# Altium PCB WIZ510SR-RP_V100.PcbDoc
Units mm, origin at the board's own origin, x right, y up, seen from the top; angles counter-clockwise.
Board outline 63 x 45 mm, 4 copper layers (Top Layer, Internal Plane 1, Internal Plane 2, Bottom Layer); 101 components, 119 nets, 372 pads, 369 vias.
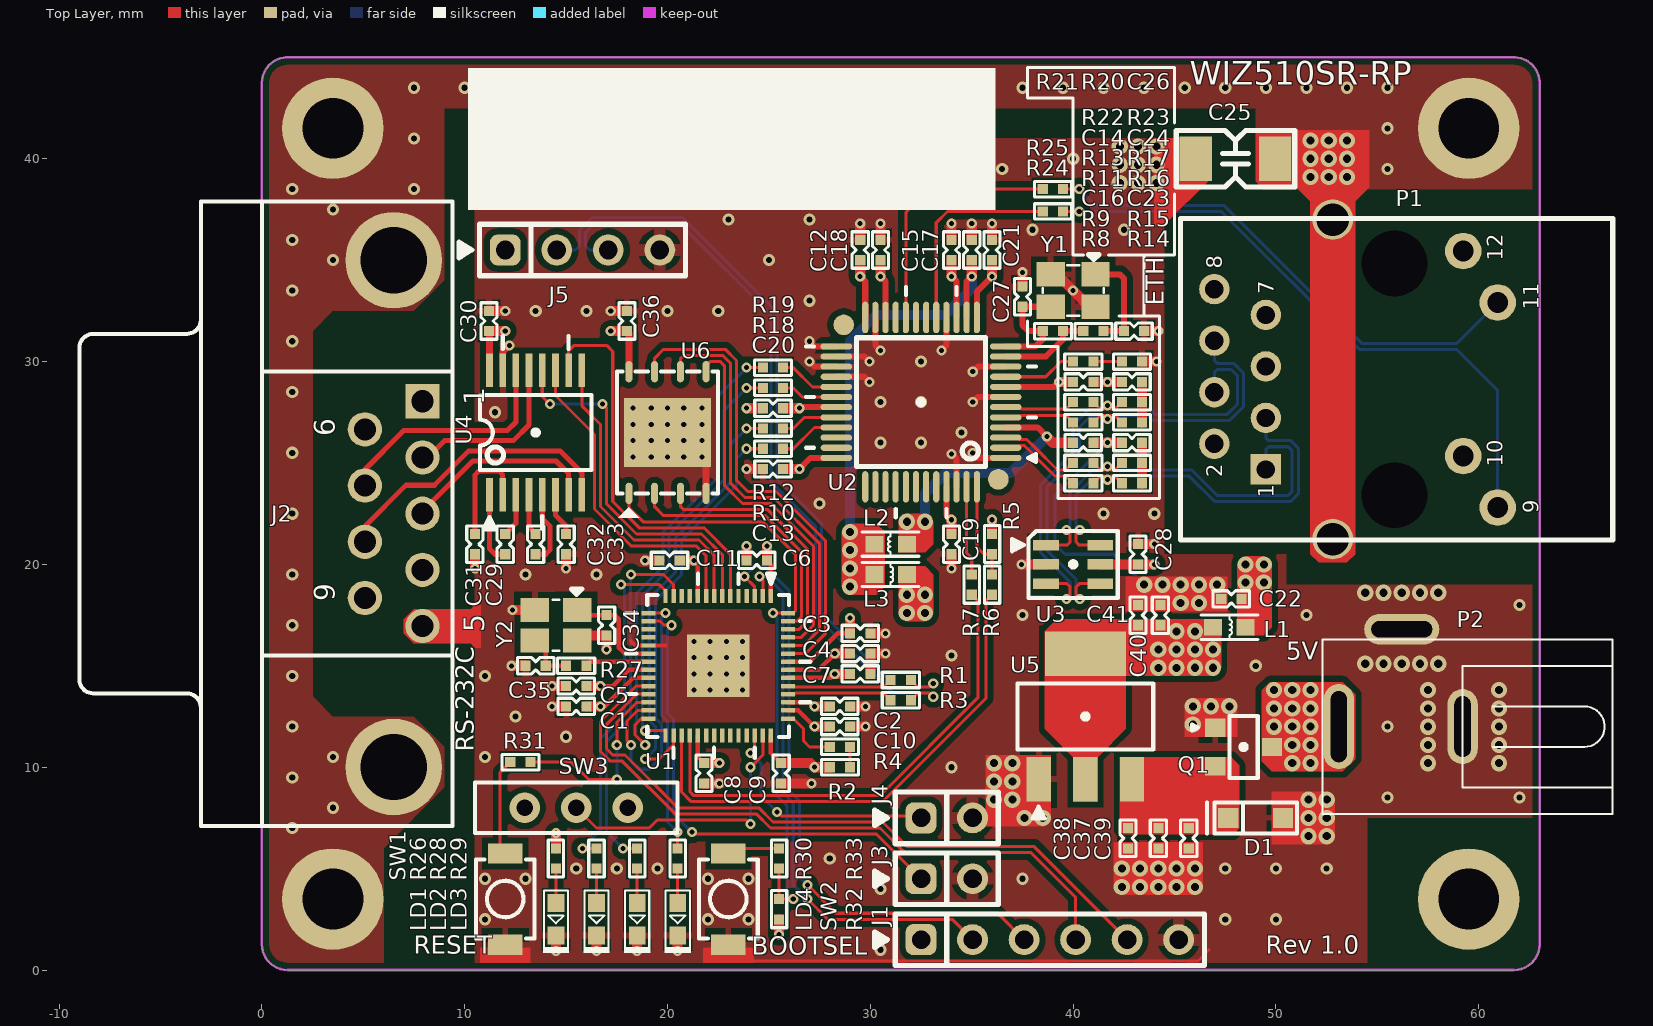
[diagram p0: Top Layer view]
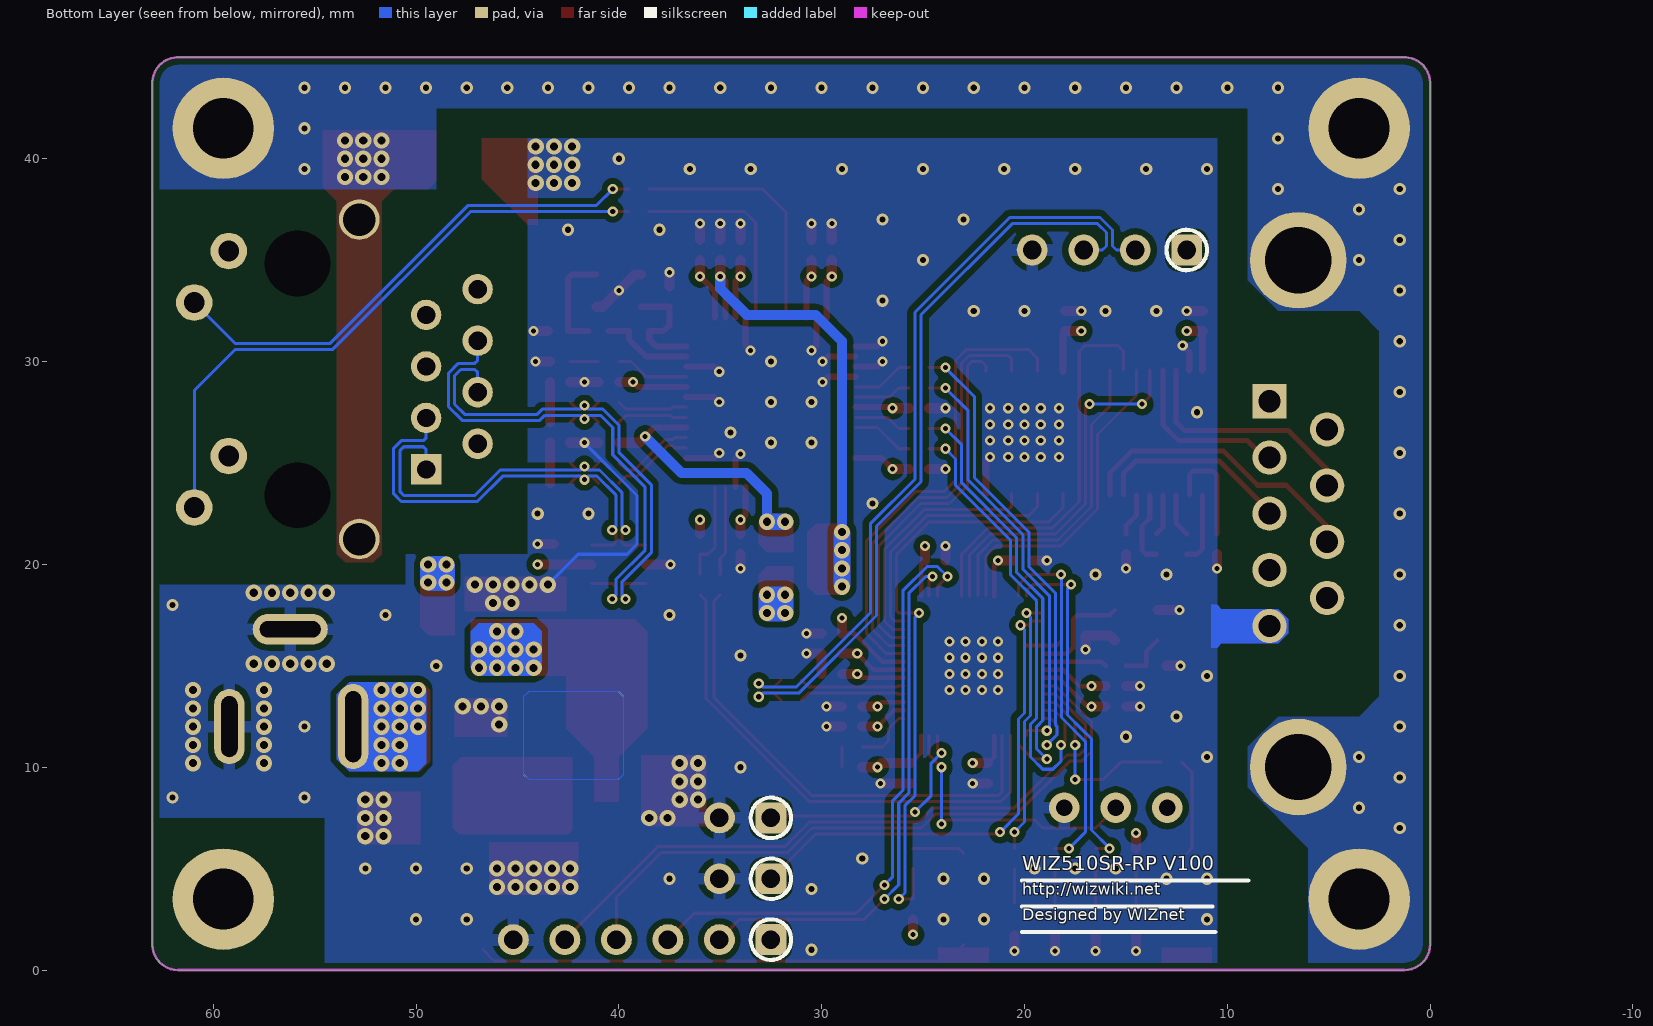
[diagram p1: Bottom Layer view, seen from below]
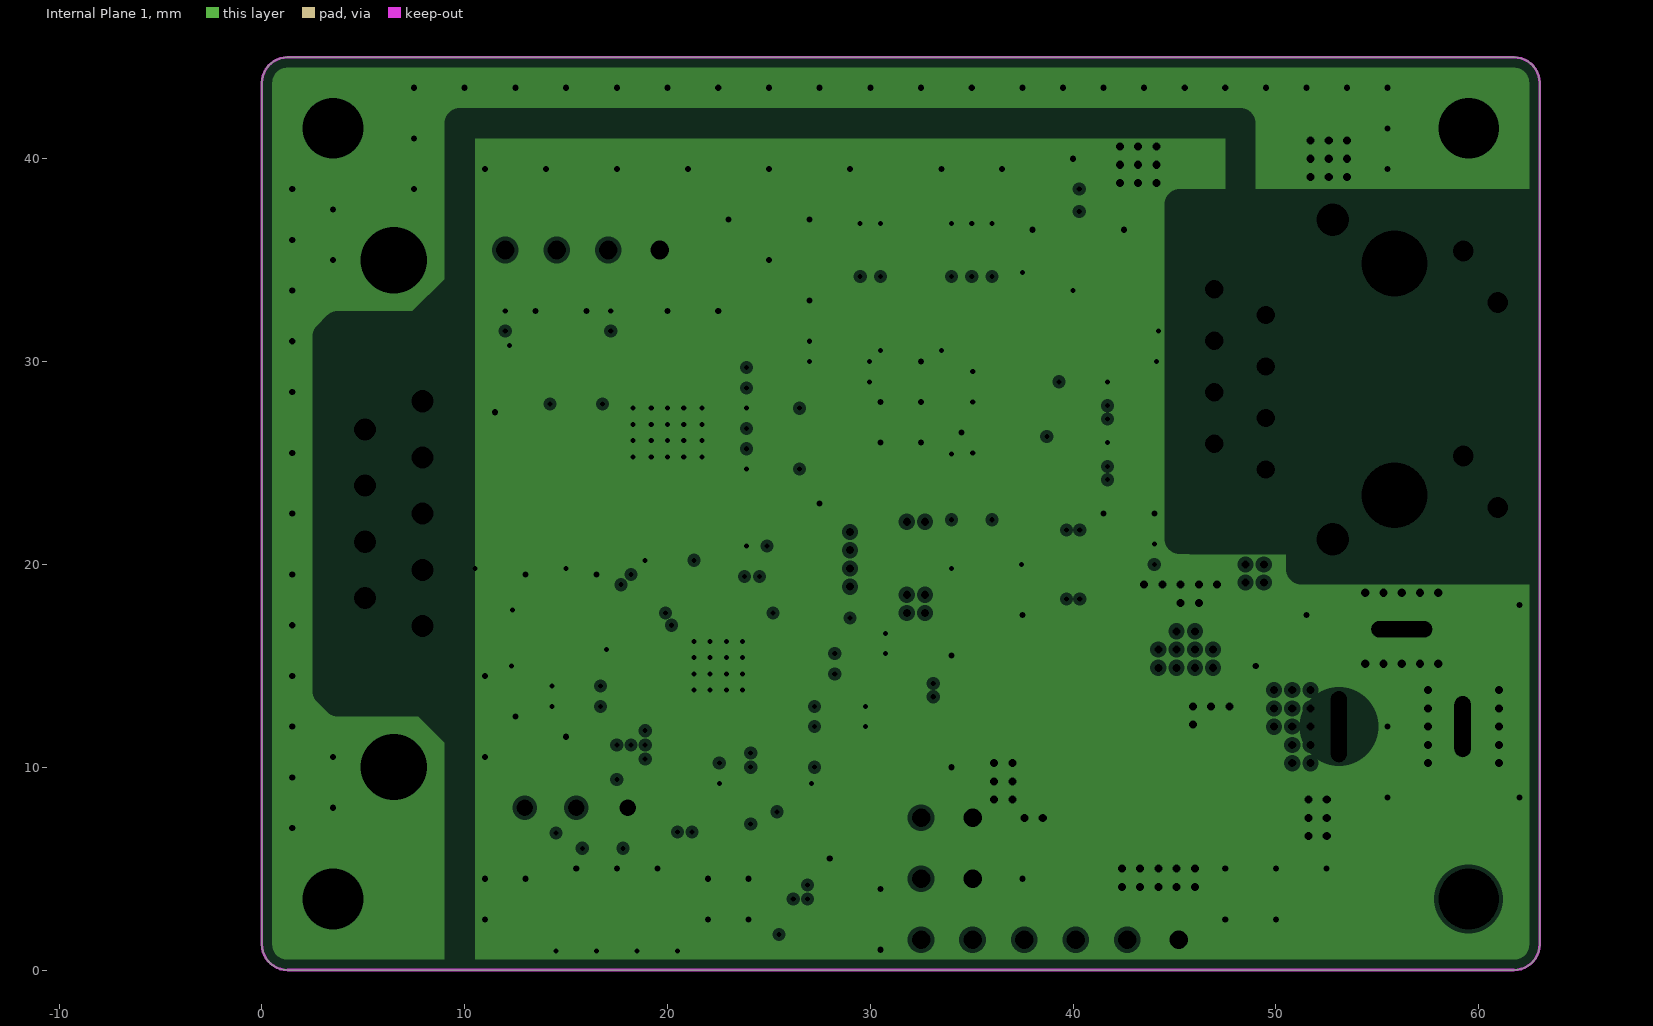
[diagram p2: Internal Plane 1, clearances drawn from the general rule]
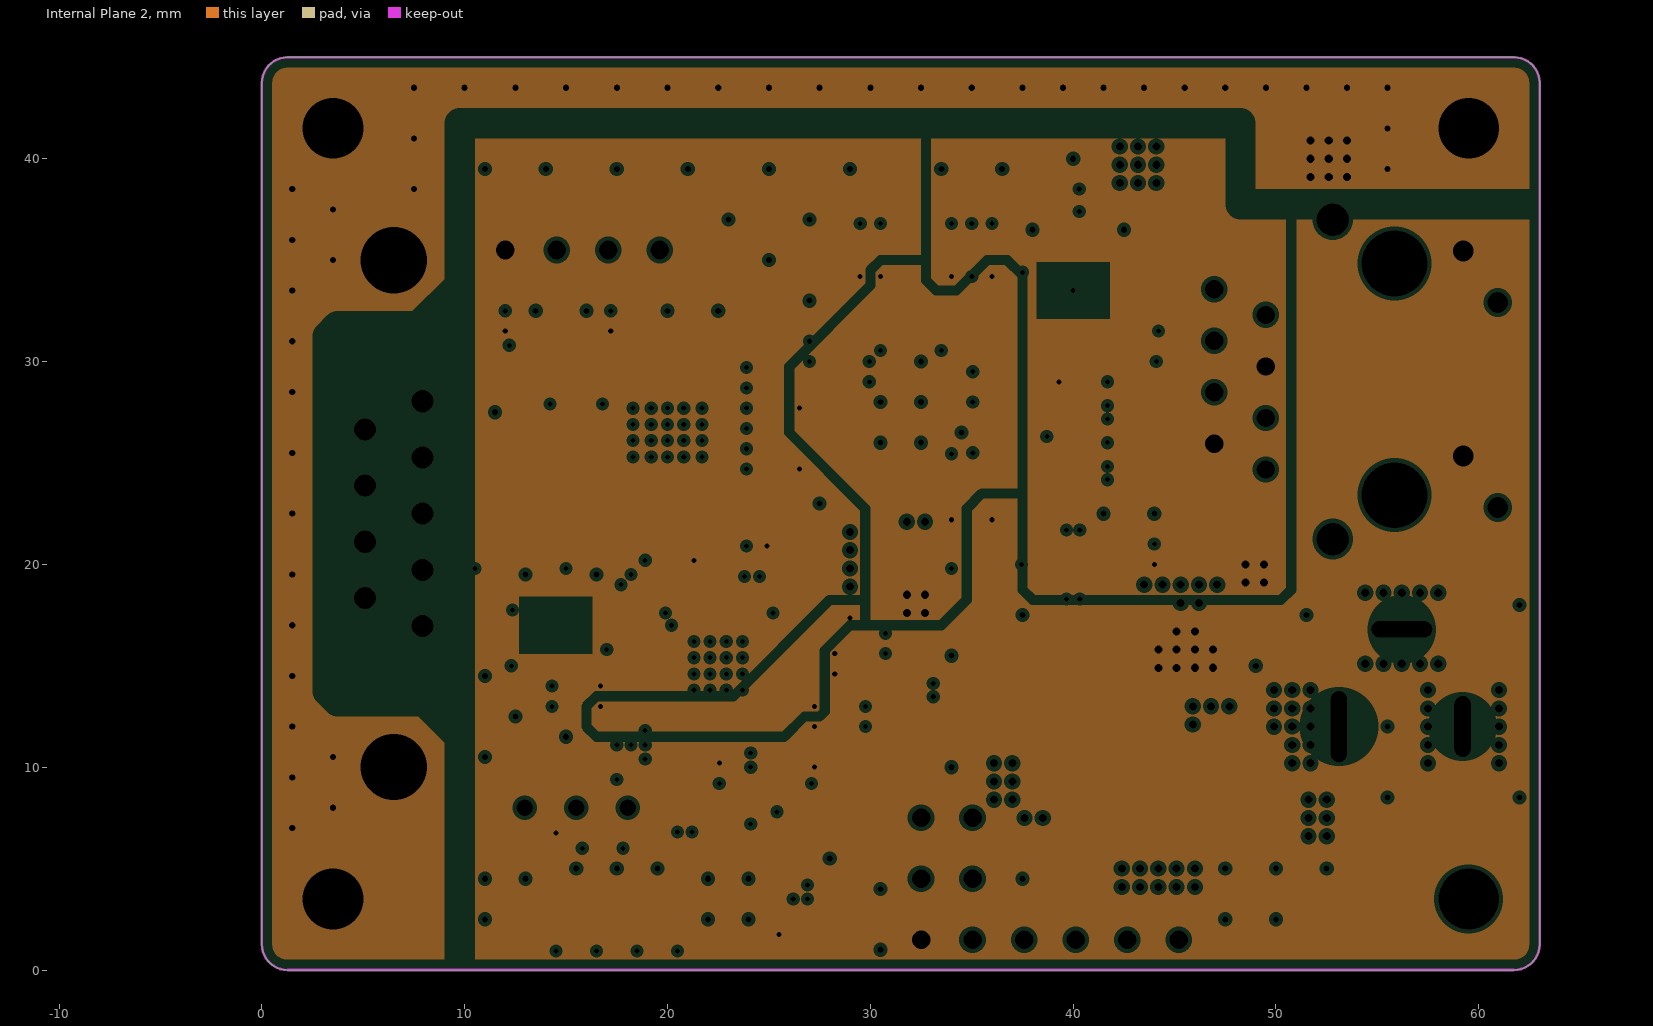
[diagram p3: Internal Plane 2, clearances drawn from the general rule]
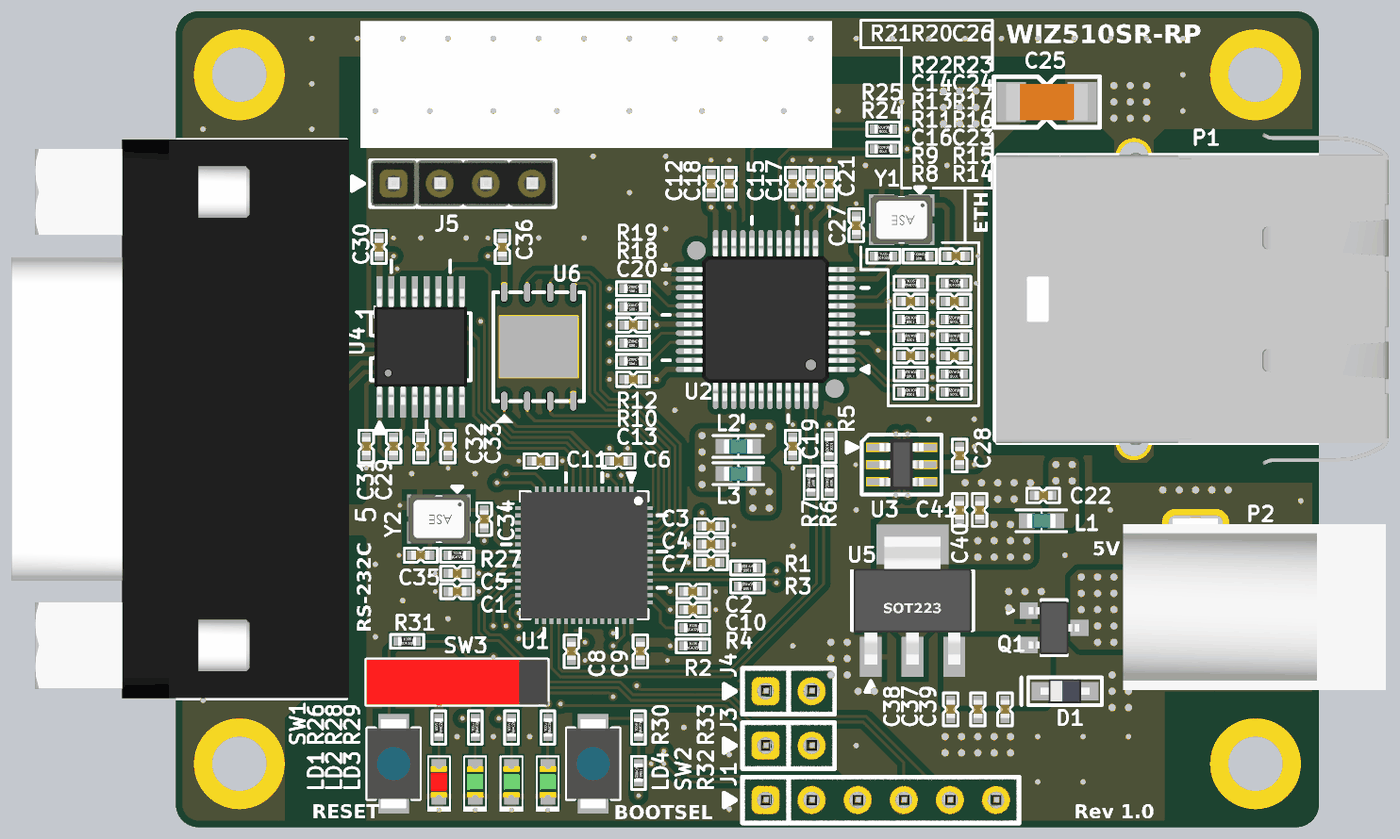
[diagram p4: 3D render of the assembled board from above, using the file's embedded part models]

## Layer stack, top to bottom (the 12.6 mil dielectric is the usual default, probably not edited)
Top Solder: solder mask 0.0102, Solder Resist, Dk 3.5
Top Layer: signal copper 0.0356
Dielectric1: core 0.32, FR-4, Dk 4.8
Internal Plane 1: plane copper 0.0356, net GND
Dielectric5: prepreg 0.32, FR-4, Dk 4.8
Internal Plane 2: plane copper 0.0356, net 3V3
Dielectric6: core 0.32, FR-4, Dk 4.8
Bottom Layer: signal copper 0.0356
Bottom Solder: solder mask 0.0102, Solder Resist, Dk 3.5

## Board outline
0,1.27 0,43.73 cw(c1.27,43.73) 1.27,45 61.73,45 cw(c61.73,43.73) 63,43.73 63,1.27 cw(c61.73,1.27) 61.73,0 1.27,0 cw(c1.27,1.27)

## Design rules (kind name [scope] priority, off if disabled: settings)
Clearance [All] p1: gap=0.15 ignorepadtopadclearanceinfootprint=FALSE except(0: Arc-Hole Track-Hole SMDPad-Hole THPad-Hole Via-Hole Fill-Hole Poly-Hole Region-Hole Text-Hole; 0.3: Arc-Poly Track-Poly SMDPad-Poly THPad-Poly Via-Poly Fill-Poly Poly-Poly Poly-Region Poly-Text)
DiffPairsRouting [All] p1: maxlimit=0.15 minlimit=0.15 mostfreqgap=0.15 toplayer_minwidth=0.15 toplayer_maxwidth=0.15 toplayer_prefwidth=0.15 bottomlayer_minwidth=0.15 bottomlayer_maxwidth=0.15 bottomlayer_prefwidth=0.15 maxuncoupledlength=15.24
HoleSize [All] p1: absolutevalues=TRUE maxlimit=4.064 minlimit=0.025 maxpercent=80.000 minpercent=20.000
PlaneClearance [All] p1: clearance=0.2
PlaneConnect [All] p1: planeconnectstyle=Direct reliefexpansion=0.508 reliefentries=4 reliefconductorwidth=0.254 reliefairgap=0.254
PolygonConnect [All] p1: thpad.connectstyle=Relief thpad.reliefconductorwidth=0.6 thpad.reliefentries=4 thpad.polygonreliefangle="90 Angle" thpad.airgapwidth=0.3 smdpad.connectstyle=Relief smdpad.reliefconductorwidth=0.3 smdpad.reliefentries=4 smdpad.polygonreliefangle="90 Angle" smdpad.airgapwidth=0.3 via.connectstyle=Direct via.reliefconductorwidth=0.254 via.reliefentries=4 via.polygonreliefangle="90 Angle" via.airgapwidth=0.254
RoutingVias [All] p1: holewidth=0.25 width=0.5 viastyle="Through Hole" minholewidth=0.25 minwidth=0.5 maxholewidth=0.4 maxwidth=0.8
SolderMaskExpansion [All] p1: expansion=0 istentingtop=FALSE
Width [All] p1: maxlimit=3 minlimit=0.1 preferedwidth=0.15
26 further rules are at their usual default settings.

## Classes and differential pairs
differential pair USB_U1: +NetR1_2 -NetR3_2
differential pair USB: +USB_DM -USB_DP
differential pair RX_U2: +NetR11_2 -NetR13_2
differential pair TX_U2: +NetR8_2 -NetR9_2
differential pair TX: +TX_P -TX_N
differential pair RX: +RX_P -RX_N

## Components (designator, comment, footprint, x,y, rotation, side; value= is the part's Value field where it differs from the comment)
C1 "1uF" CAP-0402 15.5,13 r0 top
C2 "0.1uF" CAP-0402 28.5,13 r180 top
C3 "0.1uF" CAP-0402 29.5,16.6 r180 top
C4 "1uF" CAP-0402 29.5,15.6 r180 top
C5 "0.1uF" CAP-0402 15.5,14 r0 top
C6 "0.1uF" CAP-0402 24.4,20.2 r0 top
C7 "0.1uF" CAP-0402 29.5,14.6 r180 top
C8 "0.1uF" CAP-0402 21.8,9.7 r90 top
C9 "0.1uF" CAP-0402 25.6,9.7 r90 top
C10 "0.1uF" CAP-0402 28.5,12 r180 top
C11 "0.1uF" CAP-0402 20.1,20.2 r0 top
C12 "0.1uF" CAP-0402 29.5,35.5 r270 top
C13 "0.1uF" CAP-0402 25.2,24.7 r0 top
C14 "0.1uF" CAP-0402 40.5,29 r180 top
C15 "0.1uF" CAP-0402 34,35.5 r270 top
C16 "0.1uF" CAP-0402 40.5,26 r180 top
C17 "1uF" CAP-0402 35,35.5 r270 top
C18 "0.1uF" CAP-0402 30.5,35.5 r270 top
C19 "0.1uF" CAP-0402 34,21 r90 top
C20 "0.1uF" CAP-0402 25.2,27.7 r0 top
C21 "0.1uF" CAP-0402 36,35.5 r270 top
C22 "0.1uF" CAP-0402 47.8,18.3 r0 top
C23 "0.1uF" CAP-0402 42.9,26 r0 top
C24 "0.1uF" CAP-0402 42.9,29 r0 top
C25 "1nF/2kV" CAP-1808 48,40 r0 top
C26 "18pF" CAP-0402 43,31.5 r180 top
C27 "18pF" CAP-0402 37.5,33.2 r270 top
C28 "0.1uF" CAP-0402 43.2,20.5 r270 top
C29 "0.1uF" CAP-0402 12,21 r90 top
C30 "0.1uF" CAP-0402 11.2,32 r270 top
C31 "0.1uF" CAP-0402 10.5,21 r90 top
C32 "0.1uF" CAP-0402 13.5,21 r270 top
C33 "0.1uF" CAP-0402 15,21 r90 top
C34 "15pF" CAP-0402 17,17 r270 top
C35 "15pF" CAP-0402 13.5,15 r180 top
C36 "0.1uF" CAP-0402 18,32 r270 top
C37 "1uF" CAP-0402 44.2,6.5 r90 top
C38 "1uF" CAP-0402 42.7,6.5 r90 top
C39 "0.1uF" CAP-0402 45.7,6.5 r90 top
C40 "1uF" CAP-0402 44.3,17.5 r270 top
C41 "0.1uF" CAP-0402 43.2,17.5 r270 top
D1 "BAT60A" SOD-323(1-C,2-A) 49,7.5 r180 top
J1 "2.54mm 1x6 Pin Header DIP" IDC-1X6 32.5,1.5 r0 top
J2 "D-SUB9-MALE" D-SUB9-MALE -3,22.5 r90 top locked
J3 "2.54mm 1x2 Pin Header DIP" IDC-1X2 32.5,4.5 r0 top
J4 "2.54mm 1x2 Pin Header DIP" IDC-1X2 32.5,7.5 r0 top
J5 "2.54mm 1x4 Pin Header DIP" IDC-1X4 12,35.5 r0 top
L1 "HH-1M1608-121JT" IND-0603 47.7,16.9 r0 top
L2 "HH-1M1608-121JT" IND-0603 31,21 r180 top
L3 "HH-1M1608-121JT" IND-0603 31,19.5 r0 top
LD1 "Red" LED-0603-RED 14.5,2.5 r270 top
LD2 "Green" LED-0603-GREEN 16.5,2.5 r270 top
LD3 "Green" LED-0603-green 18.5,2.5 r270 top
LD4 "Green" LED-0603-GREEN 20.5,2.5 r270 top
P1 "J1B1211CCD" RJ45-J1B1211CCD 63.65,29.125 r90 top locked
P2 "DC-JACK 2pi" "DC-JACK 2pi" 63,12 r90 top locked
Q1 "IRLML6402" SOT-23-3L 48.4,11 r270 top
R1 "0R" RES-0402 31.5,14.3 r180 top
R2 "200R" RES-0402 28.5,10 r0 top
R3 "0R" RES-0402 31.5,13.3 r180 top
R4 "1R" RES-0402 28.5,11 r0 top
R5 "4.7K" RES-0402 36,21 r270 top
R6 "0R" RES-0402 36,19 r270 top
R7 "0R" RES-0402 35,19 r270 top
R8 "3.3R" RES-0402 40.5,24 r180 top
R9 "3.3R" RES-0402 40.5,25 r180 top
R10 "0R" RES-0402 25.2,25.7 r180 top
R11 "3.3R" RES-0402 40.5,27 r180 top
R12 "0R" RES-0402 25.2,26.7 r180 top
R13 "3.3R" RES-0402 40.5,28 r180 top
R14 "49.9R" RES-0402 42.9,24 r180 top
R15 "49.9R" RES-0402 42.9,25 r180 top
R16 "49.9R" RES-0402 42.9,27 r180 top
R17 "49.9R" RES-0402 42.9,28 r180 top
R18 "0R" RES-0402 25.2,28.7 r180 top
R19 "0R" RES-0402 25.2,29.7 r180 top
R20 "0R" RES-0402 41,31.5 r180 top
R21 "1M" RES-0402 39,31.5 r0 top
R22 "12K/1%" RES-0402 40.5,30 r0 top
R23 "300R" RES-0402 42.9,30 r0 top
R24 "470R" RES-0402 39,37.4 r180 top
R25 "470R" RES-0402 39,38.5 r180 top
R26 "470R" RES-0402 14.5,5.5 r90 top
R27 "1K" RES-0402 15.5,15 r0 top
R28 "470R" RES-0402 16.5,5.5 r90 top
R29 "470R" RES-0402 18.5,5.5 r90 top
R30 "470R" RES-0402 20.5,5.5 r90 top
R31 "1K" RES-0402 12.75,10.25 r0 top
R32 "NC" RES-0402 25.5,3 r270 top
R33 "1K" RES-0402 25.5,5.5 r90 top
SW1 "1185SA(2.0)" ST-1185S 12,3.5 r270 top
SW2 "1185SA(2.0)" ST-1185S 23,3.5 r270 top
SW3 "ITS-12H" ITS-12H 15.5,8 r180 top
U1 "RP2040" QFN56(0.4/7X7) 22.5,15 r270 top
U2 "W5100S" LQFP48(0.5/9.0) 32.5,28 r180 top
U3 "TPD4S009DBKR" SOT-23-6L 40,20 r0 top
U4 "SP3232EBEY" TSSOP16(0.65/6.4) 13.5,26.5 r90 top
U5 "AME8815BEGT330Z" SOT-223 40.6,12.5 r0 top
U6 "W25Q16JVZPIM" WSON8(6X5_1.27) 20,26.5 r90 top
Y1 "25MHz" OSC-82J0626 40,33.5 r180 top
Y2 "12MHz" OSC-TZ1067B 14.5,17 r180 top

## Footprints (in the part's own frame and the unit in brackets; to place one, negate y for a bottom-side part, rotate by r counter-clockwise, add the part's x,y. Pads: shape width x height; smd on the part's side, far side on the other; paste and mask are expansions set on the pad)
CAP-0402 [mm]
  rect 0.5x0.5 smd: 1(-0.5,0) 2(0.5,0)
  silkscreen extent -0.9,-0.4 0.9,0.4, body extent -0.48,-0.25 0.52,0.25, height 0.6
CAP-1808 [mm] "Ceramic CAP 1808(4520)"
  rect 1.6x2.2 smd: 1(-1.95,0) 2(1.95,0)
  silkscreen extent -2.92,-1.4 2.92,1.4, body extent -2.25,-1.02 2.25,1.01, height 2
D-SUB9-MALE [mm] "D-SUB9, MALE, Right Angle;"
  rect 1.69x1.69 hole 1.09: 1(5.54,-10.92)
  round 1.69 hole 1.09: 2(2.77,-10.92) 3(0,-10.92) 4(-2.77,-10.92) 5(-5.54,-10.92) 6(4.155,-8.08) 7(1.385,-8.08) 8(-1.385,-8.08) 9(-4.155,-8.08)
  round 4.76 hole 3.26: 10(-12.495,-9.5) 11(12.495,-9.5)
  silkscreen extent -15.4,-12.4 15.4,6, body extent -15.38,-12.55 15.43,6.05, height 12.57
"DC-JACK 2pi" [mm] "DC-JACK 2pi"
  oval 4.2x1.5 hole 0.8 slot 3.5 at 0 deg: 1(0,9.9)
  oval 1.5x3.7 hole 0.8 slot 3 at 90 deg: 2(4.8,6.8)
  oval 3.7x1.5 hole 0.8 slot 3 at 0 deg: 3(0,3.8)
  silkscreen extent -4.3,-3.6 4.3,10.7, body extent -4.42,-3.69 5.05,10.79, height 11.18
IDC-1X2 [mil]
  rrect50% 60x60 hole 36: 1(0,0)
  round 60 hole 36: 2(100,0)
  silkscreen extent -90,-50 150,50, body extent -49,-49 151,51, height 336
IDC-1X4 [mil]
  rrect50% 60x60 hole 36: 1(0,0)
  round 60 hole 36: 2(100,0) 3(200,0) 4(300,0)
  silkscreen extent -90,-50 350,50, body extent -49,-49 351,51, height 336
IDC-1X6 [mil] "6-Way 2.54 mm Male Header"
  rrect50% 60x60 hole 36: 1(0,0)
  round 60 hole 36: 2(100,0) 3(200,0) 4(300,0) 5(400,0) 6(500,0)
  silkscreen extent -90,-50 550,50, body extent -49,-49 551,51, height 336
IND-0603 [mm] "Inductor 0603(1608)"
  rect 0.89x0.82 smd: 1(-0.8,0) 2(0.8,0)
  Top Layer pour cut-out: -0.254,0.508 -0.254,-0.508 0.254,-0.508 0.254,0.508
  silkscreen extent -1.4,-0.6 1.4,0.6, body extent -0.8,-0.4 0.8,0.4, height 0.95
ITS-12H [mm] "Through Hole Slide Switch SPDT On-On 500mA Slide"
  round 1.5 hole 0.8: 1(0,0) 2(2.54,0) 3(-2.54,0)
  silkscreen extent -5,-1.25 5,1.25, body extent -5,-1.25 5,1.25, height 6.4
LED-0603-GREEN [mm] "LED-0603-GREEN"
  rect 0.89x0.82 smd: 1(-0.8,0) 2(0.8,0)
  silkscreen extent -1.41,-0.65 1.65,0.65, body extent -0.85,-0.45 0.85,0.45, height 0.9
LED-0603-green [mm] "LED-0603-GREEN"
  rect 0.89x0.82 smd: 1(-0.8,0) 2(0.8,0)
  silkscreen extent -1.41,-0.65 1.65,0.65, body extent -0.85,-0.45 0.85,0.45, height 0.9
LED-0603-RED [mm] "LED-0603-RED"
  rect 0.89x0.82 smd: 1(-0.8,0) 2(0.8,0)
  silkscreen extent -1.41,-0.65 1.65,0.65, body extent -0.85,-0.45 0.85,0.45, height 0.9
LQFP48(0.5/9.0) [mm]
  round 1.016 smd: 0(-3.81,3.81) 0(3.81,-3.81)
  oval 1.55x0.3 smd: 1(-4.175,2.75) 2(-4.175,2.25) 3(-4.175,1.75) 4(-4.175,1.25) 5(-4.175,0.75) 6(-4.175,0.25) 7(-4.175,-0.25) 8(-4.175,-0.75) 9(-4.175,-1.25) 10(-4.175,-1.75) 11(-4.175,-2.25) 12(-4.175,-2.75) 25(4.175,-2.75) 26(4.175,-2.25) 27(4.175,-1.75) 28(4.175,-1.25) 29(4.175,-0.75) 30(4.175,-0.25) 31(4.175,0.25) 32(4.175,0.75) 33(4.175,1.25) 34(4.175,1.75) 35(4.175,2.25) 36(4.175,2.75)
  oval 0.3x1.55 smd: 13(-2.75,-4.175) 14(-2.25,-4.175) 15(-1.75,-4.175) 16(-1.25,-4.175) 17(-0.75,-4.175) 18(-0.25,-4.175) 19(0.25,-4.175) 20(0.75,-4.175) 21(1.25,-4.175) 22(1.75,-4.175) 23(2.25,-4.175) 24(2.75,-4.175) 37(2.75,4.175) 38(2.25,4.175) 39(1.75,4.175) 40(1.25,4.175) 41(0.75,4.175) 42(0.25,4.175) 43(-0.25,4.175) 44(-0.75,4.175) 45(-1.25,4.175) 46(-1.75,4.175) 47(-2.25,4.175) 48(-2.75,4.175)
  silkscreen extent -5.67,-5.67 5.68,5.68, body extent -4.5,-4.5 4.5,4.5, height 1.5
OSC-82J0626 [mm]
  rect 1.4x1.2 smd: 1(-1.1,-0.8) 2(1.1,-0.8) 3(1.1,0.8) 4(-1.1,0.8)
  silkscreen extent -1.5,-1.78 1.5,1.25, body extent -1.7,-1.35 1.7,1.35, height 1.06
OSC-TZ1067B [mm]
  rect 1.4x1.2 smd: 1(-1.05,-0.75) 2(1.05,-0.75) 3(1.05,0.75) 4(-1.05,0.75)
  silkscreen extent -1.27,-1.78 0.15,1.25, body extent -1.7,-1.35 1.7,1.35, height 1.06
QFN56(0.4/7X7) [mm]
  rect 0.7x0.22 smd: 1(-3.44,2.6) 2(-3.44,2.2) 3(-3.44,1.8) 4(-3.44,1.4) 5(-3.44,1) 6(-3.44,0.6) 7(-3.44,0.2) 8(-3.44,-0.2) 9(-3.44,-0.6) 10(-3.44,-1) 11(-3.44,-1.4) 12(-3.44,-1.8) 13(-3.44,-2.2) 14(-3.44,-2.6) 29(3.44,-2.6) 30(3.44,-2.2) 31(3.44,-1.8) 32(3.44,-1.4) 33(3.44,-1) 34(3.44,-0.6) 35(3.44,-0.2) 36(3.44,0.2) 37(3.44,0.6) 38(3.44,1) 39(3.44,1.4) 40(3.44,1.8) 41(3.44,2.2) 42(3.44,2.6)
  rect 0.22x0.7 smd: 15(-2.6,-3.44) 16(-2.2,-3.44) 17(-1.8,-3.44) 18(-1.4,-3.44) 19(-1,-3.44) 20(-0.6,-3.44) 21(-0.2,-3.44) 22(0.2,-3.44) 23(0.6,-3.44) 24(1,-3.44) 25(1.4,-3.44) 26(1.8,-3.44) 27(2.2,-3.44) 28(2.6,-3.44) 43(2.6,3.44) 44(2.2,3.44) 45(1.8,3.44) 46(1.4,3.44) 47(1,3.44) 48(0.6,3.44) 49(0.2,3.44) 50(-0.2,3.44) 51(-0.6,3.44) 52(-1,3.44) 53(-1.4,3.44) 54(-1.8,3.44) 55(-2.2,3.44) 56(-2.6,3.44)
  rect 3.1x3.1 smd: 57(0,0)
  silkscreen extent -4.54,-4.54 4.54,4.54, body extent -3.5,-3.5 3.5,3.5, height 0.8
RES-0402 [mm]
  rect 0.5x0.5 smd: 1(-0.5,0) 2(0.5,0)
  silkscreen extent -0.91,-0.38 0.91,0.38, body extent -0.5,-0.25 0.5,0.25, height 0.35
RJ45-J1B1211CCD [mm]
  rect 1.5x1.5 hole 0.9: 1(-4.445,14.15)
  round 1.5 hole 0.9: 2(-3.175,16.69) 3(-1.905,14.15) 4(-0.635,16.69) 5(0.635,14.15) 6(1.905,16.69) 7(3.175,14.15) 8(4.445,16.69)
  round 1.8 hole 1.02: 9(-6.325,2.72) 10(-3.785,4.42) 11(3.785,2.72) 12(6.325,4.42)
  round 2 hole 1.6: 13(-7.875,10.85) 14(7.875,10.85)
  round 1.8 hole 3.25: ""(-5.715,7.8) ""(5.715,7.8)
  silkscreen extent -7.93,-2.95 7.93,18.35, body extent -9.16,-3.2 9.16,18.64, height 15.09
SOD-323(1-C,2-A) [mm]
  rect 1x1 smd: 1(1.35,0) 2(-1.35,0)
  silkscreen extent -2.03,-0.76 2.4,0.76, body extent -1.35,-0.68 1.35,0.67, height 0.79
SOT-23-3L [mm]
  rect 0.9x1 smd: 1(-0.95,-1.4) 2(0.95,-1.4) 3(0,1.4)
  silkscreen extent -1.53,-2.55 1.53,0.7, body extent -1.45,-1.4 1.45,1.4, height 1.28
SOT-23-6L [mm]
  rect 1.27x0.508 smd paste-0.07: 1(-1.34,0.95) 2(-1.34,0) 3(-1.34,-0.95) 4(1.34,-0.95) 5(1.34,0) 6(1.34,0.95)
  silkscreen extent -3.02,-1.65 2.2,1.65, body extent -1.21,-1.4 1.21,1.4, height 1.09
SOT-223 [mm]
  rect 1.2x2.2 smd: 1(-2.3,-3.1) 2(0,-3.1) 3(2.3,-3.1)
  rect 4x2.2 smd: 4(0,3.1)
  silkscreen extent -3.35,-5.03 3.35,1.63, body extent -3.25,-3.53 3.25,3.52, height 1.82
ST-1185S [mm]
  rect 1x1.7 smd: 1(-2.25,0) 2(2.25,0)
  silkscreen extent -1.95,-1.45 1.95,1.45, body extent -2.45,-1.45 2.45,1.45, height 2
TSSOP16(0.65/6.4) [mil]
  rect 65x13 smd: 1(-121.04,89.57) 2(-121.04,63.98) 3(-121.04,38.39) 4(-121.04,12.8) 5(-121.04,-12.8) 6(-121.04,-38.39) 7(-121.04,-63.98) 8(-121.04,-89.57) 9(121.04,-89.57) 10(121.04,-63.98) 11(121.04,-38.39) 12(121.04,-12.8) 13(121.04,12.8) 14(121.04,38.39) 15(121.04,63.98) 16(121.04,89.57)
  silkscreen extent -188,-108 187,108, body extent -126,-100 126,100, height 47
WSON8(6X5_1.27) [mm]
  oval 1.05x0.35 smd mask+0.05: 1(-3,1.905) 2(-3,0.635) 3(-3,-0.635) 4(-3,-1.905) 5(3,-1.905) 6(3,-0.635) 7(3,0.635) 8(3,1.905)
  rect 3.4x4.3 smd mask+0.05: 9(0,0)
  silkscreen extent -4.2,-2.5 3,2.5, body extent -3,-2.5 3,2.5, height 0.8

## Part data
C1 C2 C3 C4 C5 C6 C7 C8 C9 C10 C11 C12 C13 C14 C15 C16 C17 C18 C19 C20 C21 C22 C23 C24 C26 C27 C28 C29 C30 C31 C32 C33 C34 C35 C36 C37 C38 C39 C40 C41: library part CAP-0402, "Ceramic CAP 0402(1005)"
C25: library part CAP-1808, "Ceramic CAP 1808(4520)"
D1: library part DIODE-BAT60A, "Silicon Schottky Diode"
J2: "D-SUB-9, MALE,  Right Angle", PackageDocument=O
L1 L2 L3: library part IND-0603, "Inductor 0603(1608)"
LD1 LD2 LD3 LD4: library part LED-0603, "LED-0603"
Q1: library part Q-IRLML6402, "HEXFET Power MOSFET"
R1 R2 R3 R4 R5 R6 R7 R8 R9 R10 R11 R12 R13 R14 R15 R16 R17 R18 R19 R20 R21 R22 R23 R24 R25 R26 R27 R28 R29 R30 R31 R32 R33: library part RES-0402, "RES-0402"
SW1 SW2: library part ITS-1107(SMD), "TACT Switch (SMD)"
SW3: "Slide Switch"
U1: "Raspverry Pi, Dual ARM Cortex-M0+ @ 133MHz"
U2: "WIZnet Hardwired TCP/IP Chip"
U3: "4-Channel ESD Solution for High-Speed Differential Interface"
U4: "True +3.0V to +5.5V RS-232 Transceivers"
U5: "1.5A CMOS LDO"
U6: "3V 16M-BIT / SERIAL FLASH MEMORY WITH / DUAL/QUAD SPI, QPI & DTR"
Y1: library part OSC-82J0626-25MHz, "X-tal 25MHz,3.2x2.5 SMD, CL=18pF"
Y2: library part OSC-TZ1067B-12MHz, "X-tal 12MHz,3.2x2.5 SMD, CL=20pF"

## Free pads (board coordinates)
  round 5 hole 3: 0(3.5,3.5) 0(3.5,41.5) 0(59.5,3.5) 0(59.5,41.5)

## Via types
v1: diameter 0.5, hole 0.25, Top Layer to Bottom Layer, tented both sides, 153 vias
v2: diameter 0.8, hole 0.4, Top Layer to Bottom Layer, tented both sides, 110 vias
v3: diameter 0.6, hole 0.3, Top Layer to Bottom Layer, tented both sides, 106 vias

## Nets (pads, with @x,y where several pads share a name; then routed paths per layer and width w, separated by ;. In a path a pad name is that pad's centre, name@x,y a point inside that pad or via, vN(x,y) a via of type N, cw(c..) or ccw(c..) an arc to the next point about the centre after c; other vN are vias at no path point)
1V1: C1.2 C2.2 C3.2 U1.23 U1.45 U1.50 | length 10.2
  Top Layer w0.22: v1(16.7,13) 16.9,13 18.3,14.4 U1.23 ; U1.45 27.046,13.2 v1(27.246,13) ; U1.50 27,15.2 28.4,16.6 C3.2
  Top Layer w0.5: C1.2 v1(16.7,13) ; v1(27.246,13) C2.2 ; C3.2 v1(29,17.354)
1V2A: C16.2 L2.1 U2.4 | length 13.1
  Top Layer w0.3: U2.4 38.25,26.75 v1(38.7,26.3)
  Top Layer w0.5: v1(38.7,26.3) 39,26 C16.2
  Bottom Layer w0.5: v2(32.7,22.1) 32.7,23.5 33.7,24.5 36.9,24.5 v1(38.7,26.3)
  Bottom Layer w0.8: v2(31.8,22.1) v2(32.7,22.1)
1V2D: C18.2 C19.2 C20.2 C21.2 L3.2 U2.13 U2.22 U2.31 U2.45 | length 11.1
  Top Layer w0.3: v1(26.5,27.7) 26.55,27.75 U2.31 ; v1(30.5,34.2) 30.75,33.95 U2.22 ; U2.45 33.75,22.45 v1(34,22.2) ; U2.13 35.25,33.45 v1(36,34.2)
  Top Layer w0.5: C20.2 v1(26.5,27.7) ; v1(30.5,34.2) C18.2 ; C19.2 v1(34,22.2) ; v1(36,34.2) C21.2
  other v2: 31.8,17.6 32.7,17.6 31.8,18.5 32.7,18.5
1V2O: C17.2 L2.2 L3.1 U2.14 | length 20
  Top Layer w0.3: U2.14 34.75,33.95 v1(35,34.2)
  Top Layer w0.5: v1(35,34.2) C17.2
  Bottom Layer w0.5: v2(29,21.6) 29,31 30.3,32.3 33.7,32.3 35,33.6 v1(35,34.2)
  other v2: 29,18.9 29,19.8 29,20.7
3V3: C4.2 C5.2 C6.2 C7.2 C8.2 C9.2 C10.2 C11.2 C12.2 C13.2 C30.2 C36.2 C40.2 C41.2 J1.1 J5.1 L1.1 P1.10 P1.12 R2.1 R5.1 R26.2 R32.2 U1.1 U1.10 U1.22 U1.33 U1.42 U1.44 U1.48 U1.49 U2.24 U2.36 U4.16 U5.2 U5.4 U6.8 | length 37
  Top Layer w0.22: v1(16.7,14) 17.3,14 18.1,14.8 U1.22 ; v1(21.3,20.2) 21.5,20 U1.10 ; U1.33 21.5,10.5 C8.2 ; C6.2 25.1,20 U1.1 ; U1.42 25.1,10.7 C9.2 ; U1.44 26.446,12.8 v1(27.246,12) ; U1.48 28.046,14.4 v1(28.246,14.6) ; U1.49 27.446,14.8 v1(28.246,15.6)
  Top Layer w0.3: v1(26.5,24.7) 27.05,25.25 U2.36 ; v1(29.5,34.2) 29.75,33.95 U2.24
  Top Layer w0.33: U4.16 C30.2@11.225,31.275
  Top Layer w0.35: C36.2 18.095,31.405 U6.8
  Top Layer w0.5: C30.2 v1(12,31.5) ; R26.2 v1(14.5,6.754) ; C5.2 v1(16.7,14) ; v1(17.2,31.5) C36.2 ; C11.2 v1(21.3,20.2) ; C8.2 v1(22.554,10.2) ; C6.2 v1(24.9,20.9) ; v1(25.5,1.746) R32.2 ; C9.2 27.046,10.2 v1(27.246,10) R2.1 ; C13.2 v1(26.5,24.7) ; v1(27.246,12) C10.2 ; v1(28.246,14.6) C7.2 ; v1(28.246,15.6) C4.2 ; v1(29.5,34.2) C12.2 ; R5.1 v1(36,22.2)
  other v2: 44.2,14.9 45.1,14.9 46,14.901 46.9,14.901 44.2,15.8 45.1,15.8 46,15.8 46.9,15.8 45.1,16.7 46,16.7
3V3A: C14.2 C15.2 C22.2 C28.2 L1.2 P1.2 P1.5 U2.8 U2.15 U3.5 | length 9
  Top Layer w0.3: v1(34,34.2) 34.25,33.95 U2.15 ; U2.8 39.05,28.75 v1(39.3,29)
  Top Layer w0.5: v1(34,34.2) C15.2 ; v1(39.3,29) C14.2 ; U3.5 C28.2 v1(44,20)
  other v2: 48.5,19.1 49.4,19.1 48.5,20 49.4,20
5V: C37.2 C38.2 C39.2 D1.1 Q1.2 U5.3
ACTn: R25.2 U2.20 | length 12.4
  Top Layer w0.15: U2.20 31.75,37.35 32.9,38.5 R25.2
ADC_VREF: R2.2 R4.2 | length 1
  Top Layer w0.15: R2.2 R4.2
BLINK: R30.2 U1.15 | length 12.9
  Top Layer w0.15: U1.15 v1(19.9,17.6) ; R30.2 v1(20.5,6.8)
  Bottom Layer w0.15: v1(19.9,17.6) 19.7,17.4 19.7,12.549 20,12.249 20,7.3 v1(20.5,6.8)
BOOTSEL: R32.1 R33.1 U1.56 U6.1 | length 30.5
  Top Layer w0.15: U6.1 18.095,22.805 18.8,22.1 24.7,22.1 26.3,20.5 26.3,17.7 26.2,17.6 U1.56 v1(25.2,17.6) ; R33.1 R32.1 v1(26.2,3.5)
  Bottom Layer w0.15: v1(25.2,17.6) 25.4,17.4 25.4,8.6 25.9,8.1 25.9,3.8 v1(26.2,3.5)
CHGND: C25.2 J2.10 J2.11 P1.13 P1.14 pad.0@3.5,3.5 pad.0@3.5,41.5 pad.0@59.5,41.5
  other v2: 51.7,39.1 52.6,39.1 53.5,39.1 51.7,40 52.6,40 53.5,40 51.7,40.9 52.6,40.9 53.5,40.9
  other v3: 1.5,7 3.5,8 1.5,9.5 3.5,10.5 1.5,12 1.5,14.5 1.5,17 1.5,19.5 1.5,22.5 1.5,25.5 1.5,28.5 1.5,31 1.5,33.5 3.5,35 1.5,36 3.5,37.5 1.5,38.5 7.5,38.5 55.5,39.5 7.5,41 55.5,41.5 7.5,43.5 10,43.5 12.5,43.5 15,43.5 17.5,43.5 20,43.5 22.5,43.5 25,43.5 27.5,43.5 30,43.5 32.5,43.5 35,43.5 37.5,43.5 39.5,43.5 41.5,43.5 43.5,43.5 45.5,43.5 47.5,43.5 49.5,43.5 51.5,43.5 53.5,43.5 55.5,43.5
FACT_RST: J4.1 U1.40 | length 11.6
  Top Layer w0.15: v1(24.1,10.7) 24.3,10.9 U1.40 ; v1(25.4,7.8) 25.6,7.6 32.4,7.6 J4.1
  Bottom Layer w0.15: v1(24.1,10.7) 24.6,10.2 24.6,8.6 v1(25.4,7.8)
GND: C1.1 C2.1 C3.1 C4.1 C5.1 C6.1 C7.1 C8.1 C9.1 C10.1 C11.1 C12.1 C13.1 C14.1 C15.1 C16.1 C17.1 C18.1 C19.1 C20.1 C21.1 C22.1 C23.1 C24.1 C25.1 C26.1 C27.1 C28.1 C30.1 C31.1 C33.1 C34.2 C35.2 C36.1 C37.1 C38.1 C39.1 C40.1 C41.1 D1.2 J1.6 J2.5 J3.2 J4.2 J5.4 LD1.2 LD2.2 LD3.2 LD4.2 P2.2 P2.3 Q1.1 R23.2 SW1.2 SW2.2 SW3.3 U1.19 U1.57 U2.1 U2.7 U2.10 U2.16 U2.23 U2.25 U2.26 U2.27 U2.28 U2.46 U3.2 U4.15 U5.1 U6.4 U6.9 Y1.2 Y1.4 Y2.2 Y2.4 | length 92.2
  Top Layer w0.15: SW2.2 23.8,0.45 46.15,0.45 46.7,1
  Top Layer w0.22: 18.2,16.2 18.4,16 U1.19 19.9,16
  Top Layer w0.3: v1(27,30) 27.25,29.75 U2.27 ; v1(27,31) 27.25,30.75 U2.25 ; U2.28 29.7,29.25 v1(29.95,29) ; U2.26 29.7,30.25 v1(29.95,30) ; U2.23 30.25,30.8 v1(30.5,30.55) ; v1(33.5,30.55) 33.75,30.8 U2.16 ; v1(34,25.45) 34.25,25.2 U2.46 ; v1(35.05,25.5) 35.3,25.25 U2.1 ; v1(35.05,28) 35.3,28.25 U2.7 ; v1(35.05,29.5) 35.3,29.75 U2.10
  Top Layer w0.33: U4.15 11.875,30.475 v1(12.2,30.8)
  Top Layer w0.35: v1(21.7,25.3) 21.905,25.095 U6.4
  Top Layer w0.5: v1(10.5,19.8) C31.1 ; C30.1 v1(12,32.5) ; v1(12.3,15) C35.2 ; v1(12.35,17.75) Y2.2 ; v1(14.3,13) C1.1 ; v1(14.3,14) C5.1 ; v1(14.5,0.946) LD1.2 ; v1(15,19.8) C33.1 ; Y2.4 15.8,16.5 C34.2 v1(17,15.8) ; v1(16.5,0.946) LD2.2 ; v1(17.2,32.5) C36.1 ; v1(18.5,0.946) LD3.2 ; v1(18.9,20.2) C11.1 ; v1(20.5,0.946) LD4.2 ; C8.1 v1(22.554,9.2) ; C6.1 v1(23.9,20.9) ; v1(23.9,24.7) C13.1 ; v1(23.9,27.7) C20.1 ; C9.1 v1(27.1,9.2) ; C10.1 v1(29.754,12) ; C2.1 v1(29.754,13) ; C12.1 v1(29.5,36.8) ; C7.1 C4.1@30,15.354 ; C4.1 v1(30.754,15.6) ; C3.1 v1(30.754,16.6) ; C18.1 v1(30.5,36.8) ; v1(34,19.8) C19.1 ; C15.1 v1(34,36.8) ; C17.1 v1(35,36.8) ; C21.1 v1(36,36.8) ; v1(37.46,20) U3.2 ; C27.1 v1(37.5,34.4) ; Y1.2 39.2,34.3 v1(40,33.5) 40.8,32.7 Y1.4 ; C16.1 v1(41.7,26) C23.1 ; C14.1 v1(41.7,29) C24.1 ; C28.1 v1(44,21) ; R23.2 v1(44.1,30) ; C26.1 v1(44.2,31.5)
  Bottom Layer w0.15: v1(41.7,26) 39.1,23.4 39.1,21 39.6,20.5 42,20.5 v2(43.5,19)
  other v1: 21.3,13.8 22.1,13.8 22.9,13.8 23.7,13.8 21.3,14.6 22.1,14.6 22.9,14.6 23.7,14.6 21.3,15.4 22.1,15.4 22.9,15.4 23.7,15.4 21.3,16.2 22.1,16.2 22.9,16.2 23.7,16.2 18.3,25.3 19.2,25.3 20,25.3 20.8,25.3 18.3,26.1 19.2,26.1 20,26.1 20.8,26.1 21.7,26.1 18.3,26.9 19.2,26.9 20,26.9 20.8,26.9 21.7,26.9 18.3,27.7 19.2,27.7 20,27.7 20.8,27.7 21.7,27.7
  other v2: 42.4,4.1 43.3,4.1 44.2,4.1 45.1,4.1 46,4.1 42.4,5 43.3,5 44.2,5 45.1,5 46,5 51.6,6.6 52.5,6.6 37.6,7.5 38.5,7.5 51.6,7.5 52.5,7.5 36.1,8.4 37,8.4 51.6,8.4 52.5,8.4 36.1,9.3 37,9.3 36.1,10.2 37,10.2 57.5,10.2 61,10.2 57.5,11.1 61,11.1 57.5,12 61,12 45.9,12.1 57.5,12.9 61,12.9 45.9,13 46.8,13 47.7,13 57.5,13.8 61,13.8 54.4,15.1 55.3,15.1 56.2,15.1 57.1,15.1 58,15.1 45.3,18.1 46.2,18.1 54.4,18.6 55.3,18.6 56.2,18.6 57.1,18.6 58,18.6 44.4,19 45.3,19 46.2,19 47.1,19 42.3,38.8 43.2,38.8 44.1,38.8 42.3,39.7 43.2,39.7 44.1,39.7 42.3,40.6 43.2,40.6 44.1,40.6
  other v3: 30.5,1 11,2.5 22,2.5 24,2.5 47.5,2.5 50,2.5 30.5,4 11,4.5 13,4.5 22,4.5 24,4.5 37.5,4.5 15.5,5 17.5,5 19.5,5 47.5,5 50,5 52.5,5 28,5.5 55.5,8.5 62,8.5 34,10 11,10.5 15,11.5 55.5,12 12.5,12.5 11,14.5 49,15 34,15.5 37.5,17.5 51.5,17.5 62,18 13,19.5 16.5,19.5 41.5,22.5 44,22.5 27.5,23 30.5,26 32.5,26 34.5,26.5 11.5,27.5 30.5,28 32.5,28 32.5,30 13.5,32.5 16,32.5 20,32.5 22.5,32.5 27,33 25,35 38,36.5 42.5,36.5 23,37 27,37 11,39.5 14,39.5 17.5,39.5 21,39.5 25,39.5 29,39.5 33.5,39.5 36.5,39.5 40,40
HW_TRIG: SW3.1 U1.41 | length 13.9
  Top Layer w0.15: SW3.1 16.5,7 19.1,7 19.5,7.4 23.9,7.4 v1(24.1,7.2) ; v1(24.1,10) 24.7,10.6 U1.41
  Bottom Layer w0.15: v1(24.1,7.2) v1(24.1,10)
INTn: R7.2 U1.32 | length 24.2
  Top Layer w0.15: U1.32 21.1,8.8 21.3,8.6 30.476,8.6 35.3,13.424 35.3,18.2 R7.2
LINK_STATUS: R29.2 U1.13 | length 17.9
  Top Layer w0.15: v1(17.8,6) R29.2 ; v1(18.2,19.5) 19.8,19.5 20.3,19 U1.13
  Bottom Layer w0.15: v1(17.8,6) 17,6.8 17,11.272 18.175,12.447 18.175,19.475 v1(18.2,19.5)
LINKn: R24.2 U2.17 | length 10.2
  Top Layer w0.15: U2.17 33.25,36.85 33.8,37.4 R24.2
NetC23_2: C23.2 R14.1 R15.1 | length 2
  Top Layer w0.5: R14.1 R15.1 C23.2
NetC24_2: C24.2 R16.1 R17.1 | length 2
  Top Layer w0.5: R16.1 R17.1 C24.2
NetC26_2: C26.2 R20.1 Y1.1 | length 5.1
  Top Layer w0.3: Y1.1 42.3,34.3 42.5,34.1 C26.2 R20.1
NetC27_2: C27.2 R21.1 U2.12 Y1.3 | length 5.8
  Top Layer w0.3: U2.12 38.15,30.75 38.5,31.1 R21.1 37.8,31.5 37.5,31.8 C27.2 Y1.3
NetC29_1: C29.1 U4.1 | length 3.5
  Top Layer w0.25: U4.1 11.225,20.775 11.5,20.5 C29.1
NetC29_2: C29.2 U4.3 | length 2.1
  Top Layer w0.25: C29.2 12.525,22.025 U4.3
NetC31_2: C31.2 U4.2 | length 5.4
  Top Layer w0.25: C31.2 10.5,24.4 10.7,24.6 11.7,24.6 11.875,24.425 U4.2
NetC32_1: C32.1 U4.4 | length 2.1
  Top Layer w0.25: U4.4 13.175,21.825 C32.1
NetC32_2: C32.2 U4.5 | length 3.7
  Top Layer w0.25: C32.2 14,20.5 14.2,20.7 14.2,21.9 13.825,22.275 U4.5
NetC33_2: C33.2 U4.6 | length 2.1
  Top Layer w0.25: U4.6 14.475,22.425 15,21.9 C33.2
NetC35_1: C35.1 R27.1 Y2.3 | length 2.5
  Top Layer w0.22: Y2.3 14,15.7 C35.1 R27.1
NetJ2_1: J2.1
NetJ2_2: J2.2 U4.13 | length 8.6
  Top Layer w0.25: J2.2 8.17,25.27 9,26.1 12.4,26.1 13.175,26.875 U4.13
NetJ2_3: J2.3 U4.7 | length 9.7
  Top Layer w0.25: J2.3 7.92,22.62 10.4,25.1 14.5,25.1 15.125,24.475 U4.7
NetJ2_4: J2.4
NetJ2_6: J2.6
NetJ2_7: J2.7 U4.14 | length 11.8
  Top Layer w0.25: J2.7 5.08,24.68 7,26.6 8.8,26.6 12.1,26.6 12.525,27.025 U4.14
NetJ2_8: J2.8 U4.8 | length 14.5
  Top Layer w0.25: J2.8 5.08,21.88 7.1,23.9 8.5,23.9 10.2,25.6 14.7,25.6 15.775,24.525 U4.8
NetJ2_9: J2.9
NetLD1_1: LD1.1 R26.1 | length 1.7
  Top Layer w0.15: LD1.1 R26.1
NetLD2_1: LD2.1 R28.1 | length 1.7
  Top Layer w0.15: LD2.1 R28.1
NetLD3_1: LD3.1 R29.1 | length 1.7
  Top Layer w0.15: LD3.1 R29.1
NetLD4_1: LD4.1 R30.1 | length 1.7
  Top Layer w0.15: LD4.1 R30.1
NetP1_7: P1.7
NetP1_8: P1.8
NetP1_9: P1.9 R24.1 | length 30.9
  Top Layer w0.15: R24.1 v1(40.3,37.4)
  Bottom Layer w0.15: v1(40.3,37.4) 47.3,37.4 54.1,30.6 58.9,30.6 60.93,28.57 P1.9
NetP1_11: P1.11 R25.1 | length 25.4
  Top Layer w0.15: R25.1 v1(40.3,38.5)
  Bottom Layer w0.15: v1(40.3,38.5) 41.1,37.7 47.424,37.7 54.224,30.9 58.92,30.9 P1.11
NetP2_1: P2.1 Q1.3
  other v2: 50.8,10.2 51.7,10.2 50.8,11.1 51.7,11.1 49.9,12 50.8,12.002 51.7,12 49.9,12.9 50.8,12.9 51.7,12.9 49.9,13.8 50.8,13.8 51.7,13.8
NetR1_2: R1.2 U1.47 | length 5.2
  Top Layer w0.15: U1.47 26.25,14 26.3,13.95 30.65,13.95 R1.2
NetR3_2: R3.2 U1.46 | length 5.2
  Top Layer w0.15: U1.46 26.25,13.6 26.3,13.65 30.65,13.65 R3.2
NetR4_1: R4.1 U1.43 | length 3
  Top Layer w0.15: U1.43 26.2,12.4 26.7,11.9 26.7,11.3 27,11 R4.1
NetR5_2: R5.2 R6.1 U2.48 | length 4.9
  Top Layer w0.15: U2.48 35.25,20.85 35.6,20.5 R5.2 R6.1
NetR7_1: R7.1 U2.47 | length 4.4
  Top Layer w0.15: U2.47 34.75,20.55 35,20.3 R7.1
NetR8_2: R8.2 U2.2 | length 4.1
  Top Layer w0.15: U2.2 37.25,25.75 37.35,25.85 37.6,25.85 37.8,25.65 39.1,24.35 39.65,24.35 R8.2
NetR9_2: R9.2 U2.3 | length 4.1
  Top Layer w0.15: U2.3 37.25,26.25 37.35,26.15 37.724,26.15 38.1,25.774 39.224,24.65 39.65,24.65 R9.2
NetR10_1: R10.1 U2.33 | length 3.1
  Top Layer w0.15: R10.1 26.2,25.7 27.25,26.75 U2.33
NetR11_2: R11.2 U2.5 | length 3.5
  Top Layer w0.15: U2.5 37.35,27.25 37.45,27.35 39,27.35 39.65,27.35 R11.2
NetR12_1: R12.1 U2.32 | length 2.9
  Top Layer w0.15: R12.1 26.2,26.7 26.75,27.25 U2.32
NetR13_2: R13.2 U2.6 | length 3.5
  Top Layer w0.15: U2.6 37.35,27.75 37.45,27.65 39,27.65 39.65,27.65 R13.2
NetR18_1: R18.1 U2.30 | length 2.8
  Top Layer w0.15: R18.1 26.2,28.7 26.65,28.25 U2.30
NetR19_1: R19.1 U2.29 | length 3
  Top Layer w0.15: R19.1 26.2,29.7 27.15,28.75 U2.29
NetR20_2: R20.2 R21.2 U2.11 | length 4.6
  Top Layer w0.3: U2.11 38.65,30.25 39.5,31.1 R21.2 R20.2
NetR22_1: R22.1 U2.9 | length 3.6
  Top Layer w0.15: U2.9 38.65,29.25 39.4,30 R22.1
NetR22_2: R22.2 R23.1 | length 1.4
  Top Layer w0.15: R22.2 R23.1
NetR31_1: R31.1 SW1.1 | length 4.8
  Top Layer w0.15: SW1.1 11.75,6 11.75,9.75 R31.1
NetR33_2: R33.2 SW2.1 | length 2.6
  Top Layer w0.15: SW2.1 23.25,6 R33.2
NetSW3_2: SW3.2
NetU1_4: U1.4
NetU1_5: U1.5
NetU1_11: U1.11
NetU1_12: U1.12
NetU1_17: U1.17
NetU1_18: U1.18
NetU1_34: U1.34
NetU1_35: U1.35
NetU1_36: U1.36
NetU1_37: U1.37
NetU1_38: U1.38
NetU1_39: U1.39
NetU2_18: U2.18
NetU2_19: U2.19
NetU2_21: U2.21
NetU2_34: U2.34
NetU2_35: U2.35
NetU2_37: U2.37
NetU2_38: U2.38
NetU2_39: U2.39
NetU2_40: U2.40
NetU2_41: U2.41
NetU2_42: U2.42
NetU2_43: U2.43
NetU2_44: U2.44
PREV_BANK: J3.1 U1.16 | length 24.3
  Top Layer w0.15: U1.16 19.628,17.2 19.828,17 v1(20.2,17) ; v1(21.2,6.8) 21.3,6.7 30.3,6.7 J3.1
  Bottom Layer w0.15: v1(20.2,17) 20,16.8 20,12.673 20.3,12.373 20.3,7.7 v1(21.2,6.8)
QSPI1_SCLK: U1.52 U6.6 | length 21
  Top Layer w0.15: U6.6 20.635,30.135 20.8,30.3 22.724,30.3 23.1,29.924 23.1,24.024 23.824,23.3 25.224,23.3 27.5,21.024 27.5,20.4 27.5,16.8 26.7,16 U1.52
QSPI1_SD0: U1.53 U6.5 | length 18.3
  Top Layer w0.15: U6.5 21.905,29.805 22.1,30 22.6,30 22.8,29.8 22.8,23.9 23.7,23 25.1,23 27.2,20.9 27.2,20.4 27.2,17 26.6,16.4 U1.53
QSPI1_SD1: U1.55 U6.2 | length 12.8
  Top Layer w0.15: U6.2 19.365,22.835 19.8,22.4 24.824,22.4 26.6,20.624 26.6,17.4 26.4,17.2 U1.55
QSPI1_SD2: U1.54 U6.3 | length 12.5
  Top Layer w0.15: U6.3 20.635,22.865 20.8,22.7 24.949,22.7 26.9,20.749 26.9,17.2 26.5,16.8 U1.54
QSPI1_SD3: U1.51 U6.7 | length 23.5
  Top Layer w0.15: U6.7 19.365,30.165 19.8,30.6 22.849,30.6 23.4,30.049 23.4,24.149 23.949,23.6 25.349,23.6 27.8,21.149 27.8,20.4 27.8,16.6 26.8,15.6 U1.51
RSTn: R6.2 U1.31 | length 25.3
  Top Layer w0.15: U1.31 20.7,8.776 21.176,8.3 30.6,8.3 35.7,13.4 35.7,18.2 R6.2
RUN: R31.2 U1.26 | length 9.4
  Top Layer w0.15: R31.2 15.25,10.25 16.1,9.4 v1(17.5,9.4) ; v1(17.5,11.1) 17.5,12.2 18.5,13.2 U1.26
  Bottom Layer w0.15: v1(17.5,9.4) v1(17.5,11.1)
RX_N: P1.6 R11.1 R16.2 U3.4 | length 26.8
  Top Layer w0.15: v1(40.325,18.3) 40.15,18.475 40.15,18.9 40.3,19.05 U3.4 ; R11.1 41.35,27.35 41.525,27.35 v1(41.7,27.175) 41.875,27.35 42.05,27.35 R16.2
  Bottom Layer w0.15: v1(40.325,18.3) 40.15,18.475 40.15,19.25 38.7,20.7 38.7,23.8 40.3,25.4 40.3,26.75 40.9,27.35 41.525,27.35 v1(41.7,27.175) 41.875,27.35 43.65,27.35 43.9,27.1 47.724,27.1 48.4,27.776 48.4,29.424 47.914,29.91 47.1,29.91 46.96,30.05 P1.6
RX_P: P1.4 R13.1 R17.2 U3.3 | length 26.3
  Top Layer w0.15: U3.3 39.7,19.05 39.85,18.9 39.85,18.475 v1(39.675,18.3) ; R13.1 41.35,27.65 41.525,27.65 v1(41.7,27.825) 41.875,27.65 42.05,27.65 R17.2
  Bottom Layer w0.15: v1(39.675,18.3) 39.85,18.475 39.85,19.126 38.4,20.576 38.4,23.924 40,25.524 40,26.874 40.776,27.65 41.525,27.65 v1(41.7,27.825) 41.875,27.65 43.774,27.65 44.024,27.4 47.6,27.4 48.1,27.9 48.1,29.3 47.79,29.61 47.1,29.61 46.96,29.47 P1.4
SPI0_CSn: R19.2 U1.28 | length 23.9
  Top Layer w0.15: v1(18.9,11.1) 18.4,11.6 18.4,12.1 18.7,12.4 U1.28 ; v1(23.9,29.7) R19.2
  Bottom Layer w0.15: v1(18.9,11.1) 18.4,11.6 18.4,12 18.475,12.075 18.475,18.583 19.775,19.883 19.775,21.583 22.475,24.283 22.475,28.275 v1(23.9,29.7)
SPI0_RX: R10.2 U1.27 | length 23.2
  Top Layer w0.15: v1(18.2,11.1) 18,11.3 18,12.276 18.524,12.8 U1.27 ; v1(23.9,25.7) R10.2
  Bottom Layer w0.15: v1(18.2,11.1) 18.2,10.3 18.6,9.9 19.1,9.9 19.7,10.5 19.7,12.124 19.4,12.424 19.4,18.2 20.7,19.5 20.7,21.2 23.4,23.9 23.4,25.2 v1(23.9,25.7)
SPI0_SCK: R18.2 U1.29 | length 21.1
  Top Layer w0.15: v1(18.9,11.8) 19.9,11.8 U1.29 ; v1(23.9,28.7) R18.2
  Bottom Layer w0.15: v1(18.9,11.8) 18.775,11.925 18.775,18.459 20.075,19.759 20.075,21.459 22.775,24.159 22.775,27.575 v1(23.9,28.7)
SPI0_TX: R12.2 U1.30 | length 21.6
  Top Layer w0.15: v1(18.9,10.4) 19.6,10.4 20.3,11.1 U1.30 ; v1(23.9,26.7) R12.2
  Bottom Layer w0.15: v1(18.9,10.4) 19.4,10.9 19.4,12 19.1,12.3 19.1,18.324 20.4,19.624 20.4,21.324 23.1,24.024 23.1,25.9 v1(23.9,26.7)
SWCLK: J1.4 U1.24 | length 33
  Top Layer w0.15: U1.24 18.451,14 16.7,12.249 16.7,10.776 17.176,10.3 17.776,10.3 20.376,7.7 24.376,7.7 25.076,7 30.476,7 31.676,5.8 37.9,5.8 40.12,3.58 J1.4
SWDIO: J1.5 U1.25 | length 33.4
  Top Layer w0.15: U1.25 18.476,13.6 17,12.124 17,10.9 17.3,10.6 17.9,10.6 20.5,8 24.5,8 25.2,7.3 30.6,7.3 31.8,6.1 38.06,6.1 J1.5
TCP_STATUS: R28.2 U1.14 | length 17.2
  Top Layer w0.15: v1(15.8,6) R28.2 ; v1(17.7,19) 19.6,19 19.9,18.7 U1.14
  Bottom Layer w0.15: v1(15.8,6) 16.7,6.9 16.7,11.396 17.179,11.875 17.875,12.571 17.875,18.825 v1(17.7,19)
TX_N: P1.3 R8.1 R14.2 U3.6 | length 22.8
  Top Layer w0.15: v1(40.325,21.7) 40.15,21.525 40.15,21.1 40.3,20.95 U3.6 ; R8.1 41.35,24.35 41.525,24.35 v1(41.7,24.175) 41.875,24.35 42.05,24.35 R14.2
  Bottom Layer w0.15: v1(40.325,21.7) 40.15,21.875 40.15,23.426 41.074,24.35 41.525,24.35 v1(41.7,24.175) 41.875,24.35 45.726,24.35 46.976,23.1 50.724,23.1 51.1,23.476 51.1,25.724 50.724,26.1 49.64,26.1 49.5,26.24 P1.3
TX_P: P1.1 R9.1 R15.2 U3.1 | length 22.3
  Top Layer w0.15: U3.1 39.7,20.95 39.85,21.1 39.85,21.525 v1(39.675,21.7) ; R9.1 41.35,24.65 41.525,24.65 v1(41.7,24.825) 41.875,24.65 42.05,24.65 R15.2
  Bottom Layer w0.15: v1(39.675,21.7) 39.85,21.875 39.85,23.55 40.95,24.65 41.525,24.65 v1(41.7,24.825) 41.875,24.65 45.85,24.65 47.1,23.4 50.6,23.4 50.8,23.6 50.8,25.6 50.6,25.8 49.64,25.8 49.5,25.66 P1.1
UART0_RX: J1.3 U1.3 | length 30.7
  Top Layer w0.15: v1(23.8,19.4) 24.3,18.9 U1.3 ; v1(26.9,4.2) 28.3,2.8 36.28,2.8 J1.3
  Bottom Layer w0.15: v1(23.8,19.4) 24.3,19.9 24.8,19.9 26,18.7 26,8.849 26.5,8.349 26.5,4.6 v1(26.9,4.2)
UART0_TX: J1.2 U1.2 | length 27.1
  Top Layer w0.15: v1(24.541,19.407) 24.507,19.407 24.5,19.4 24.7,19.2 U1.2 ; v1(26.9,3.5) 27.9,2.5 34.04,2.5 J1.2
  Bottom Layer w0.15: v1(24.541,19.407) 24.869,19.407 25.7,18.576 25.7,8.724 26.2,8.224 26.2,4.2 v1(26.9,3.5)
UART1_CTS: U1.8 U4.9 | length 15.7
  Top Layer w0.15: U4.9 15.775,27.825 16.7,26.9 16.7,22.851 18.351,21.2 21.551,21.2 22.3,20.451 U1.8
UART1_RTS: U1.9 U4.11 | length 16.1
  Top Layer w0.15: U4.11 14.475,28.325 16.4,26.4 16.4,22.727 18.227,20.9 21.427,20.9 21.9,20.427 U1.9
UART1_RX: U1.7 U4.12 | length 18.2
  Top Layer w0.15: U4.12 13.825,28.275 v1(14.2,27.9) ; v1(16.8,27.9) 17,27.7 17,22.976 18.476,21.5 21.676,21.5 22.7,20.476 U1.7
  Bottom Layer w0.15: v1(14.2,27.9) v1(16.8,27.9)
UART1_TX: U1.6 U4.10 | length 19.7
  Top Layer w0.15: U4.10 15.125,30.525 15.4,30.8 17,30.8 17.3,30.5 17.3,27.7 17.3,23.1 18.6,21.8 21.8,21.8 23.1,20.5 U1.6
USB_DM: J5.3 R3.1 | length 37.6
  Top Layer w0.15: R3.1 32.35,13.65 32.925,13.65 v1(33.1,13.475)
  Bottom Layer w0.15: J5.3 16.16,35.5 15.96,35.7 15.96,36.36 16.4,36.8 20.6,36.8 25.1,32.3 25.1,24.076 27.3,21.876 27.3,17.476 31.126,13.65 32.925,13.65 v1(33.1,13.475)
USB_DP: J5.2 R1.1 | length 38.1
  Top Layer w0.15: R1.1 32.35,13.95 32.925,13.95 v1(33.1,14.125)
  Bottom Layer w0.15: J5.2 15.46,35.5 15.66,35.7 15.66,36.484 16.276,37.1 20.724,37.1 25.4,32.424 25.4,24.2 27.6,22 27.6,17.6 31.25,13.95 32.925,13.95 v1(33.1,14.125)
XIN: C34.1 U1.20 Y2.1 | length 5.2
  Top Layer w0.22: Y2.1 15.8,17.5 C34.1 17.4,17.5 17.6,17.3 17.6,15.9 17.9,15.6 U1.20
XOUT: R27.2 U1.21 | length 3.1
  Top Layer w0.22: R27.2 16.2,15.2 U1.21
pads on no net: P1. U2.0

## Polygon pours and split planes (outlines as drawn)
CHGND on Top Layer "NONET_L-01_P-001" (solid, remove dead copper, pour order 28): 7.5,32.5 9,34 9,42.5 49,42.5 49,38.5 63,38.5 63,45 0,45 0,0 6,0 6,6 9,9 9,11 7.5,12.5 3.5,12.5 2.5,13.5 2.5,31.5 3.5,32.5
GND on Top Layer "NONET_L-01_P-001" (solid, remove dead copper, pour order 26): 10.5,0 10.5,41 44.5,41 44.5,20.5 50.5,20.5 50.5,19 63,19 63,7.5 54.5,7.5 54.5,0 12,0
CHGND on Bottom Layer "NONET_L-01_P-001" (solid, remove dead copper, pour order 29): 7.5,32.5 9,34 9,42.5 49,42.5 49,38.5 63,38.5 63,45 0,45 0,0 6,0 6,6 9,9 9,11 7.5,12.5 3.5,12.5 2.5,13.5 2.5,31.5 3.5,32.5
GND on Bottom Layer "NONET_L-01_P-001" (solid, remove dead copper, pour order 25): 10.5,0 10.5,41 44.5,41 44.5,20.5 50.5,20.5 50.5,19 63,19 63,7.5 54.5,7.5 54.5,0 12,0
3V3 on Bottom Layer "Top Layer-NET" (solid, remove dead copper, pour order 6): 44.704,12.319 44.704,9.652 44.45,9.398 44.323,9.398 40.005,9.398 39.751,9.652 39.751,9.779 39.751,13.462 40.005,13.716 40.259,13.716 44.45,13.716 44.704,13.462
3V3 on Internal Plane 2 (split plane): 32.498,35.252 30.5,35.252 30.435,35.244 30.374,35.218 30.344,35.196 30.322,35.178 29.822,34.678 29.782,34.626 29.756,34.565 29.748,34.5 29.748,33.854 25.822,29.928 25.782,29.876 25.756,29.815 25.748,29.75 25.748,26.5 25.756,26.435 25.782,26.374 25.822,26.322 29.498,22.646 29.498,18.502 28,18.502 27.935,18.494 27.874,18.468 27.822,18.428 23.146,13.752 16.5,13.752 16.435,13.744 16.374,13.718 16.344,13.696 16.322,13.678 15.822,13.178 15.782,13.126 15.756,13.065 15.748,13 15.748,12 15.756,11.935 15.782,11.874 15.822,11.822 16.322,11.322 16.374,11.282 16.435,11.256 16.5,11.248 25.75,11.248 25.815,11.256 25.876,11.282 25.928,11.322 26.854,12.248 27.5,12.248 27.565,12.256 27.626,12.282 27.678,12.322 27.928,12.572 27.968,12.624 27.994,12.685 28.002,12.75 28.002,15.646 28.428,16.072 29.104,16.748 33.5,16.748 33.565,16.756 33.626,16.782 33.678,16.822 34.928,18.072 34.946,18.094 34.968,18.124 34.994,18.185 35.002,18.25 35.002,22.646 35.604,23.248 37.248,23.248 37.248,18.75 37.256,18.685 37.282,18.624 37.322,18.572 37.822,18.072 37.844,18.054 37.874,18.032 37.935,18.006 38,17.998 50.25,17.998 50.315,18.006 50.376,18.032 50.428,18.072 50.928,18.572 50.946,18.594 50.968,18.624 50.994,18.685 51.002,18.75 51.002,36.998 62.49,36.998 62.49,1.27 62.491,1.257 62.482,1.151 62.455,1.035 62.409,0.924 62.346,0.822 62.269,0.731 62.178,0.654 62.076,0.591 61.965,0.545 61.849,0.518 61.743,0.509 61.73,0.51 10.502,0.51 10.502,11.5 10.502,33.75 10.502,40.998 32.498,40.998
CHGND on Internal Plane 2 (split plane): 61.849,44.482 61.965,44.455 62.076,44.409 62.178,44.346 62.269,44.269 62.346,44.178 62.409,44.076 62.455,43.965 62.482,43.849 62.491,43.743 62.49,43.73 62.49,38.502 49.002,38.502 49.002,41.75 48.993,41.868 48.965,41.982 48.92,42.092 48.859,42.192 48.782,42.282 48.692,42.359 48.592,42.42 48.482,42.465 48.368,42.493 48.25,42.502 9.75,42.502 9.632,42.493 9.518,42.465 9.408,42.42 9.308,42.359 9.218,42.282 9.141,42.192 9.08,42.092 9.035,41.982 9.007,41.868 8.998,41.75 8.998,34.062 7.438,32.502 3.75,32.502 3.632,32.493 3.518,32.465 3.486,32.452 3.408,32.42 3.308,32.359 3.218,32.282 2.718,31.782 2.641,31.692 2.58,31.592 2.548,31.514 2.535,31.482 2.507,31.368 2.498,31.25 2.498,17 2.498,13.75 2.507,13.632 2.535,13.518 2.548,13.486 2.58,13.408 2.641,13.308 2.718,13.218 3.218,12.718 3.308,12.641 3.408,12.58 3.518,12.535 3.632,12.507 3.75,12.498 7.688,12.498 8.998,11.188 8.998,0.51 1.27,0.51 1.257,0.509 1.151,0.518 1.035,0.545 0.924,0.591 0.822,0.654 0.731,0.731 0.654,0.822 0.591,0.924 0.545,1.035 0.518,1.151 0.509,1.257 0.51,1.27 0.51,43.73 0.509,43.743 0.518,43.849 0.545,43.965 0.591,44.076 0.654,44.178 0.731,44.269 0.822,44.346 0.924,44.409 1.035,44.455 1.151,44.482 1.257,44.491 1.27,44.49 61.73,44.49 61.743,44.491
1V1 on Internal Plane 2 (split plane): 29.498,17.252 29,17.252 28.935,17.244 28.874,17.218 28.822,17.178 28.072,16.428 27.572,15.928 27.532,15.876 27.506,15.815 27.498,15.75 27.498,12.854 27.396,12.752 26.75,12.752 26.685,12.744 26.624,12.718 26.594,12.696 26.572,12.678 25.646,11.752 16.604,11.752 16.252,12.104 16.252,12.896 16.604,13.248 23.25,13.248 23.315,13.256 23.376,13.282 23.428,13.322 28.104,17.998 29.498,17.998
1V2D on Internal Plane 2 (split plane): 37.248,34.146 37.248,23.752 35.5,23.752 35.435,23.744 35.374,23.718 35.322,23.678 34.572,22.928 34.532,22.876 34.506,22.815 34.498,22.75 34.498,18.354 33.396,17.252 30.002,17.252 30.002,22.75 29.994,22.815 29.968,22.876 29.928,22.928 26.252,26.604 26.252,29.646 30.178,33.572 30.218,33.624 30.244,33.685 30.252,33.75 30.252,34.396 30.604,34.748 32.498,34.748 32.498,34 32.506,33.935 32.532,33.874 32.572,33.822 33.072,33.322 33.094,33.304 33.124,33.282 33.185,33.256 33.25,33.248 34.25,33.248 34.315,33.256 34.376,33.282 34.428,33.322 35.854,34.748 36.646,34.748
3V3A on Internal Plane 2 (split plane): 47.498,37.75 47.507,37.632 47.535,37.518 47.58,37.408 47.641,37.308 47.718,37.218 47.808,37.141 47.908,37.08 48.018,37.035 48.132,37.007 48.25,36.998 50.498,36.998 50.498,18.854 50.146,18.502 38.104,18.502 37.752,18.854 37.752,34.25 37.744,34.315 37.718,34.376 37.678,34.428 36.928,35.178 36.876,35.218 36.815,35.244 36.75,35.252 35.75,35.252 35.685,35.244 35.624,35.218 35.572,35.178 34.146,33.752 33.354,33.752 33.002,34.104 33.002,40.998 47.498,40.998
CHGND on Internal Plane 1 (split plane): 61.849,44.482 61.965,44.455 62.076,44.409 62.178,44.346 62.269,44.269 62.346,44.178 62.409,44.076 62.455,43.965 62.482,43.849 62.491,43.743 62.49,43.73 62.49,38.502 49.002,38.502 49.002,41.75 48.993,41.868 48.965,41.982 48.92,42.092 48.859,42.192 48.782,42.282 48.692,42.359 48.592,42.42 48.482,42.465 48.368,42.493 48.25,42.502 9.75,42.502 9.632,42.493 9.518,42.465 9.408,42.42 9.308,42.359 9.218,42.282 9.141,42.192 9.08,42.092 9.035,41.982 9.007,41.868 8.998,41.75 8.998,34.062 7.438,32.502 3.75,32.502 3.632,32.493 3.518,32.465 3.486,32.452 3.408,32.42 3.308,32.359 3.218,32.282 2.718,31.782 2.641,31.692 2.58,31.592 2.548,31.514 2.535,31.482 2.507,31.368 2.498,31.25 2.498,17 2.498,13.75 2.507,13.632 2.535,13.518 2.548,13.486 2.58,13.408 2.641,13.308 2.718,13.218 3.218,12.718 3.308,12.641 3.408,12.58 3.518,12.535 3.632,12.507 3.75,12.498 7.688,12.498 8.998,11.188 8.998,0.51 1.27,0.51 1.257,0.509 1.151,0.518 1.035,0.545 0.924,0.591 0.822,0.654 0.731,0.731 0.654,0.822 0.591,0.924 0.545,1.035 0.518,1.151 0.509,1.257 0.51,1.27 0.51,43.73 0.509,43.743 0.518,43.849 0.545,43.965 0.591,44.076 0.654,44.178 0.731,44.269 0.822,44.346 0.924,44.409 1.035,44.455 1.151,44.482 1.257,44.491 1.27,44.49 61.73,44.49 61.743,44.491
GND on Internal Plane 1 (split plane): 47.498,38.502 45.25,38.502 45.132,38.493 45.018,38.465 44.908,38.42 44.808,38.359 44.718,38.282 44.641,38.192 44.58,38.092 44.535,37.982 44.507,37.868 44.498,37.75 44.498,21.25 44.507,21.132 44.535,21.018 44.58,20.908 44.641,20.808 44.718,20.718 44.808,20.641 44.908,20.58 45.018,20.535 45.132,20.507 45.25,20.498 50.498,20.498 50.498,19.75 50.507,19.632 50.535,19.518 50.58,19.408 50.641,19.308 50.718,19.218 50.808,19.141 50.908,19.08 51.018,19.035 51.132,19.007 51.25,18.998 62.49,18.998 62.49,1.27 62.491,1.257 62.482,1.151 62.455,1.035 62.409,0.924 62.346,0.822 62.269,0.731 62.178,0.654 62.076,0.591 61.965,0.545 61.849,0.518 61.743,0.509 61.73,0.51 10.502,0.51 10.502,11.5 10.502,33.75 10.502,40.998 47.498,40.998

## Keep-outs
Keep-Out Layer:
  the board outline again, w0.127
  text ".Layer_Name" at 9.398,49.53 h1.52

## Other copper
Top Layer:
  region net GND: 7.5,16.1 7,16.6 7,17.3 7.5,17.8 10.3,17.8 10.5,18 10.8,18 10.8,15.9 10.5,15.9 10.3,16.1 9.4,16.1
  region net GND: 21.758,0.367 24.242,0.367 24.242,1.1 21.758,1.1
  region net GND: 10.758,0.367 13.242,0.367 13.242,1.1 10.758,1.1
  region net CHGND: 49,38.9 49.4,38.5 51.1,38.5 51.7,37.9 51.7,20.5 52.1,20.1 53.5,20.1 53.9,20.5 53.9,37.9 54.6,38.6 54.6,41.4 49,41.4
  region net GND: 46.75,41 46.75,39 44.5,36.75 44,36.75 44,41
  region net 1V2A: 31.4,20.6 31.4,22.1 31.8,22.5 32.7,22.5 33.1,22.1 33.1,21 32.7,20.6
  region net 1V2D: 31.8,17.2 31.4,17.6 31.4,19.9 32.7,19.9 33.1,19.5 33.1,17.6 32.7,17.2
  region net 1V2O: 29,18.5 30.3,18.5 30.7,18.9 30.7,21.6 30.3,22 29,22 28.6,21.6 28.6,18.9
  region net GND: 38.6,7.1 38.9,7.4 38.9,10.6 35.7,10.6 35.7,7.1
  region net GND: 42.6,17.7 47.6,17.7 47.6,19.4 42.6,19.4
  region net 3V3A: 48.1,16.5 48.1,20 48.5,20.4 49.4,20.4 49.8,20 49.8,16.9 49.4,16.5
  region net 3V3: 47.3,17.3 47.3,14.9 46.9,14.5 42.6,14.5 42.6,11.9 41.2,10.5 41.2,8.3 40,8.3 40,10.5 38.6,11.9 38.6,16.7 39.2,17.3
  region net GND: 42.4,3.7 42,4.1 42,6.3 46.4,6.3 46.4,4.1 46,3.7
  region net GND: 52.5,6.2 52.9,6.6 52.9,8.4 52.5,8.8 49.8,8.8 49.8,6.2
  region net GND: 45.5,11.5 48.1,11.5 48.1,13 47.7,13.4 45.9,13.4 45.5,13
  region net NetP2_1: 49.8,9.8 49.3,10.3 49.3,13.8 49.7,14.2 53.3,14.2 53.9,13.6 53.9,10.4 53.3,9.8
  region net 5V: 47.8,10.5 48.2,10.1 48.2,7 47.9,6.7 42.5,6.7 42.3,6.9 42.3,10.5
  text ".Layer_Name" at 9.398,49.53 h1.52
Bottom Layer:
  region net GND: 7.5,16.1 7,16.6 7,17.3 7.5,17.8 10.3,17.8 10.5,18 10.8,18 10.8,15.9 10.5,15.9 10.3,16.1 9.4,16.1
  region net NetP2_1: 53.3,9.8 53.9,10.4 53.9,13.6 53.3,14.2 49.9,14.2 49.5,13.8 49.5,10.2 49.9,9.8
  region net 1V2O: 28.6,18.9 28.6,21.6 29.4,21.6 29.4,18.9
  region net 1V2D: 31.8,17.2 31.4,17.6 31.4,18.5 31.8,18.9 32.7,18.9 33.1,18.5 33.1,17.6 32.7,17.2
  region net 3V3A: 48.5,18.7 48.1,19.1 48.1,20 48.5,20.4 49.4,20.4 49.8,20 49.8,19.1 49.4,18.7
  region net 3V3: 44.2,14.5 43.8,14.9 43.8,16.7 44.2,17.1 46.9,17.1 47.3,16.7 47.3,14.9 46.9,14.5
  text ".Layer_Name" at 9.398,49.53 h1.52
Internal Plane 1 (plane layer: these items are gaps in the copper):
  pour cut-out: 45.75,20.5 63,20.5 63,37.75 45.75,37.75
  pour cut-out: 9.25,13.25 3.75,13.25 3.75,31.25 4.5,32 9.25,32 9.25,23
  lines w1.5: 9.75,0.25 9.75,41.75 48.25,41.75 48.25,37.75 ; 9.75,11.5 8,13.25 4.25,13.25 3.75,13.25 3.25,13.75 3.25,17 3.25,31.25 3.75,31.75 7.75,31.75 9.75,33.75 ; 62.75,19.75 51.25,19.75 51.25,21.25 45.25,21.25 45.25,37.75 48.25,37.75 ; 62.75,37.75 48.25,37.75
  text "GND" at 9.398,49.562 h1.52
Internal Plane 2 (plane layer: these items are gaps in the copper):
  pour cut-out: 38.2,32.1 38.2,34.9 41.8,34.9 41.8,32.1
  pour cut-out: 9.25,13.25 3.75,13.25 3.75,31.25 4.5,32 9.25,32 9.25,23
  pour cut-out: 12.7,18.4 12.7,15.6 16.3,15.6 16.3,18.4
  lines w0.5: 29.75,18.25 28,18.25 23.25,13.5 16.5,13.5 16,13 16,12 16.5,11.5 25.75,11.5 26.75,12.5 27.5,12.5 27.75,12.75 27.75,15.75 28.25,16.25 29,17 29.75,17 ; 32.75,35 30.5,35 30,34.5 30,33.75 26,29.75 26,26.5 29.75,22.75 29.75,17 ; 32.75,41.75 32.75,34 33.25,33.5 34.25,33.5 35.75,35 36.75,35 37.5,34.25 37.5,18.75 38,18.25 50.25,18.25 50.75,18.75 50.75,37.25 ; 37.5,23.5 35.5,23.5 34.75,22.75 34.75,18.25 33.5,17 29.75,17
  lines w1.5: 9.75,0.25 9.75,41.75 48.25,41.75 48.25,37.75 62.75,37.75 ; 9.75,11.5 8,13.25 4.25,13.25 3.75,13.25 3.25,13.75 3.25,17 3.25,31.25 3.75,31.75 7.75,31.75 9.75,33.75
  text "POWER" at 9.398,49.562 h1.52

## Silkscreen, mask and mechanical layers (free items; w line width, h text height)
Top Overlay:
  rectangle: 10.16,37.465 36.16,44.465
  lines w0.15: 37.75,32 37.75,31 37.75,30.75 39.25,30.75 39.25,23.25 44.25,23.25 44.25,32.25 42.25,32.25 ; 40.5,35.25 40,35.25 40,43 37.75,43 37.75,44.5 45,44.5 45,41.75 ; 41.75,35.25 43.5,35.25 ; 43.5,32.25 43.5,35.25 ; 45,38.25 45,35.25 43.5,35.25
  text ".Layer_Name" at 9.398,49.562 h1.52
  text "WIZ510SR-RP" at 45.75,43.25 h2
  text "ETH" at 44.75,32.75 h1.5 r90
  text "5V" at 50.5,15 h1.5
  text "RS-232C" at 10.75,10.75 h1.5 r90
  text "RESET" at 7.5,0.5 h1.5
  text "Rev 1.0" at 49.5,0.5 h1.5
  text "BOOTSEL" at 24.15,0.45 h1.5
Bottom Overlay:
  lines w0.2: 8.968,4.41 20.119,4.41 ; 10.594,1.87 20.119,1.87 ; 10.721,3.14 20.119,3.14
  text ".Layer_Name" at 9.398,49.53 h1.52
  text "WIZ510SR-RP V100" at 20.119,4.664 h1.2
  text "http://wizwiki.net" at 20.119,3.521 h1
  text "Designed by WIZnet" at 20.119,2.251 h1
Top Paste:
  text ".Layer_Name" at 9.398,49.53 h1.52
Bottom Paste:
  text ".Layer_Name" at 9.398,49.53 h1.52
Top Solder:
  text ".Layer_Name" at 9.398,49.53 h1.52
Bottom Solder:
  text ".Layer_Name" at 9.398,49.53 h1.52
Drill Guide:
  text ".Layer_Name" at 9.398,49.53 h1.52
Mechanical 2:
  lines w0.127: 71.831,16.129 97.993,16.129 ; 71.831,18.923 97.993,18.923 ; 0,1.27 ccw(c1.27,1.27) 1.27,0 61.73,0 ccw(c61.73,1.27) 63,1.27 63,43.73 ccw(c61.73,43.73) 61.73,45 1.27,45 ccw(c1.27,43.73) 0,43.73 0,1.27 ; 70.485,4.775 ccw(c71.196,4.775) 71.196,4.064 98.374,4.064 ccw(c98.374,4.775) 99.085,4.775 99.085,24.003 ccw(c98.374,24.003) 98.374,24.714 71.196,24.714 ccw(c71.196,24.003) 70.485,24.003 70.485,4.775
  text "BOARD NAME : WIZ510SR-RP_V100" at 0,60.706 h1.52
  text "VERSION : V100" at 0,57.912 h1.52
  text "SIZE : 63mX45mX1.6T" at 0,55.118 h1.52
  text "GERBER DATE : 2022. 05. 10." at 0,52.324 h1.52
  text "LAYER :" at 0,49.53 h1.52
  text "Layer Stack Up Detail for:" at 71.958,22.606 h1.02
  text "WIZ510SR-RP_V100.PcbDoc" at 71.831,20.193 h1.27
  text "Layer Name : 4L  1.6T" at 71.958,17.018 h1.02
  text "Top Layer" at 71.831,13.335 h1.52
  text "GND" at 71.831,10.541 h1.52
  text "POWER" at 71.831,7.874 h1.52
  text "Bottom Layer" at 71.831,5.334 h1.52
  text "KS Technology artwork" at 70.485,0 h5.08
Drill Drawing:
  text ".Layer_Name" at 9.398,49.53 h1.52
  text ".Legend" at 72.517,27.432 h1.02

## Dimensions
0,1.27 to 63,1.27 on Mechanical 2
1.27,0 to 1.27,45 on Mechanical 2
